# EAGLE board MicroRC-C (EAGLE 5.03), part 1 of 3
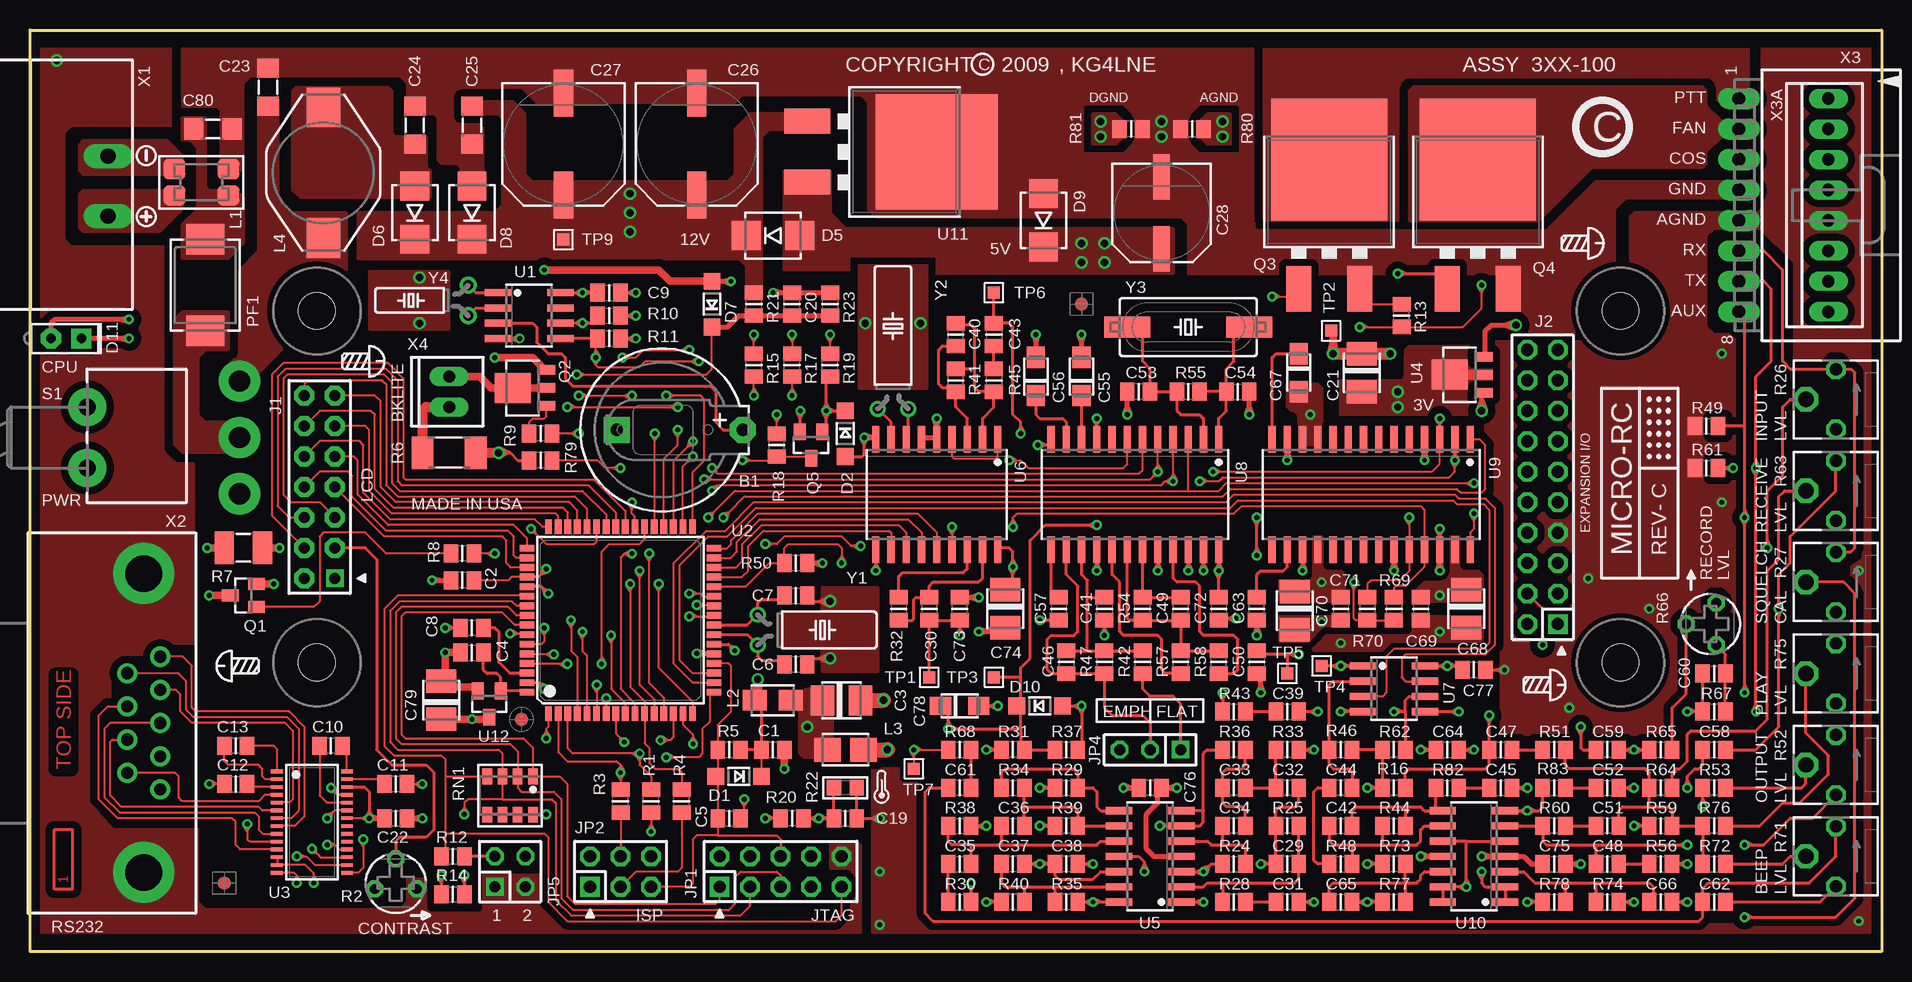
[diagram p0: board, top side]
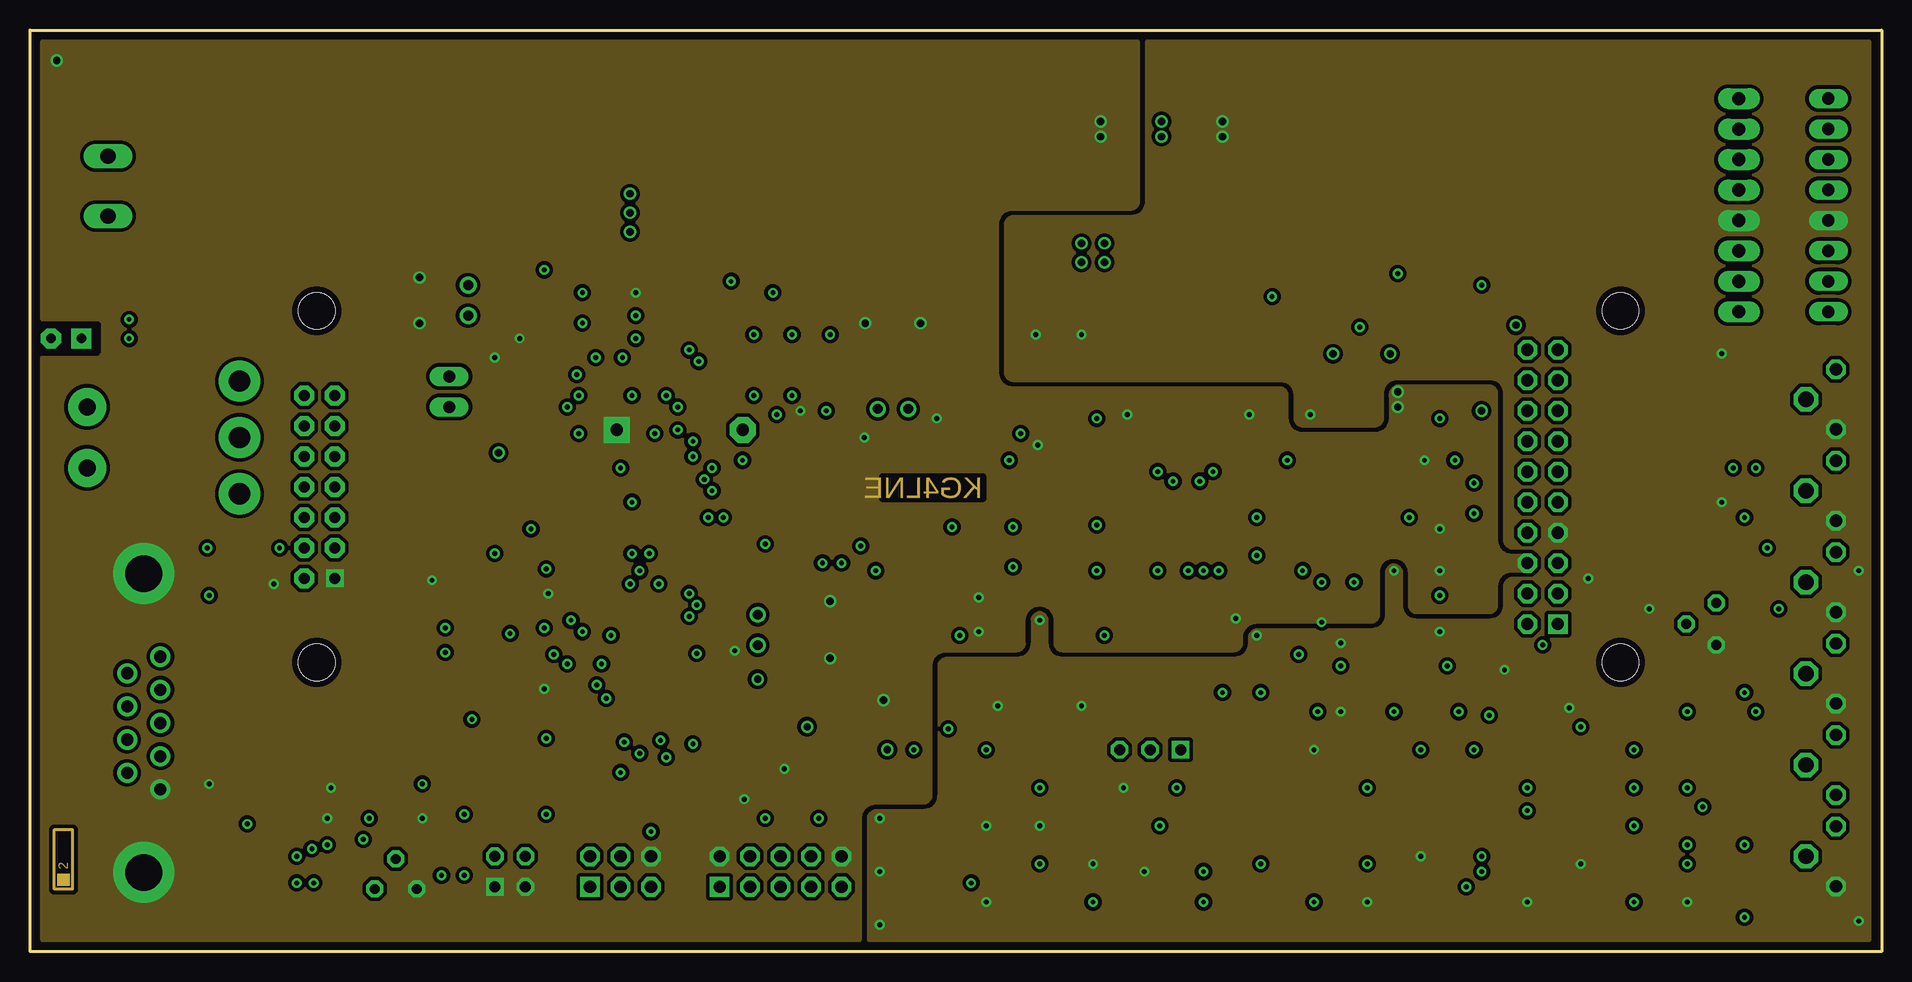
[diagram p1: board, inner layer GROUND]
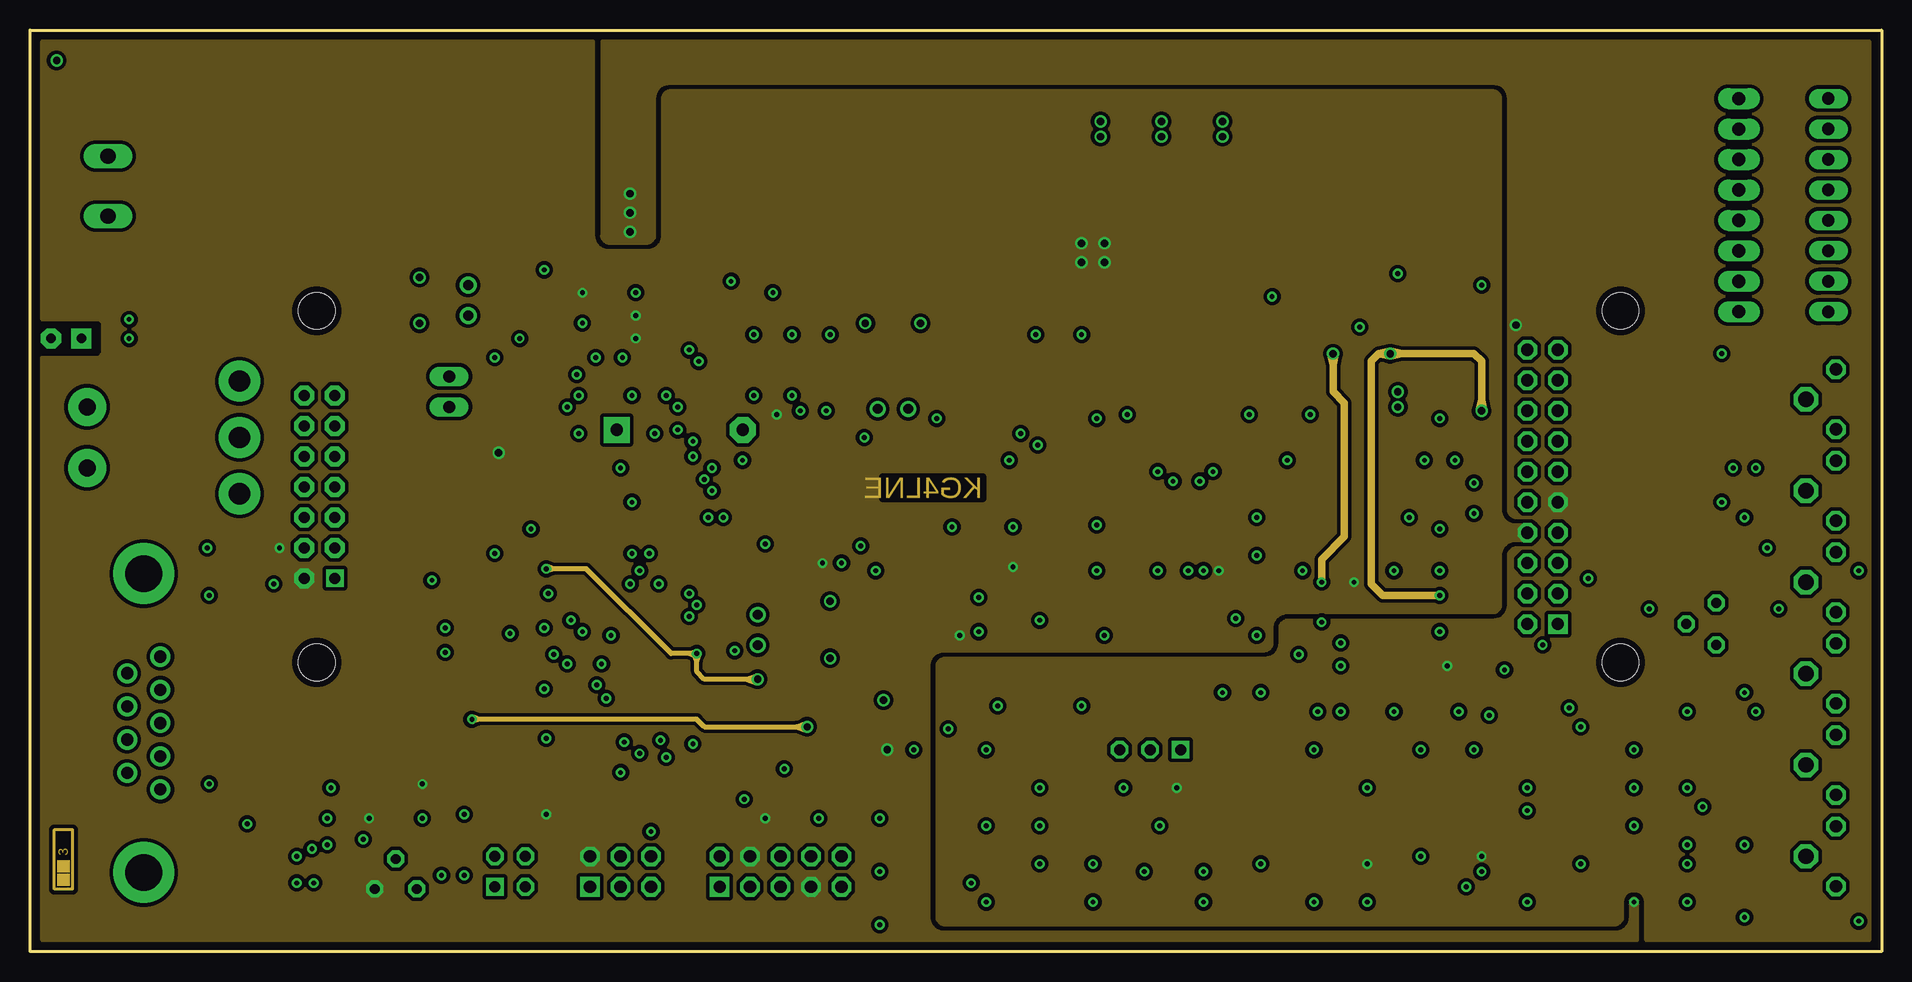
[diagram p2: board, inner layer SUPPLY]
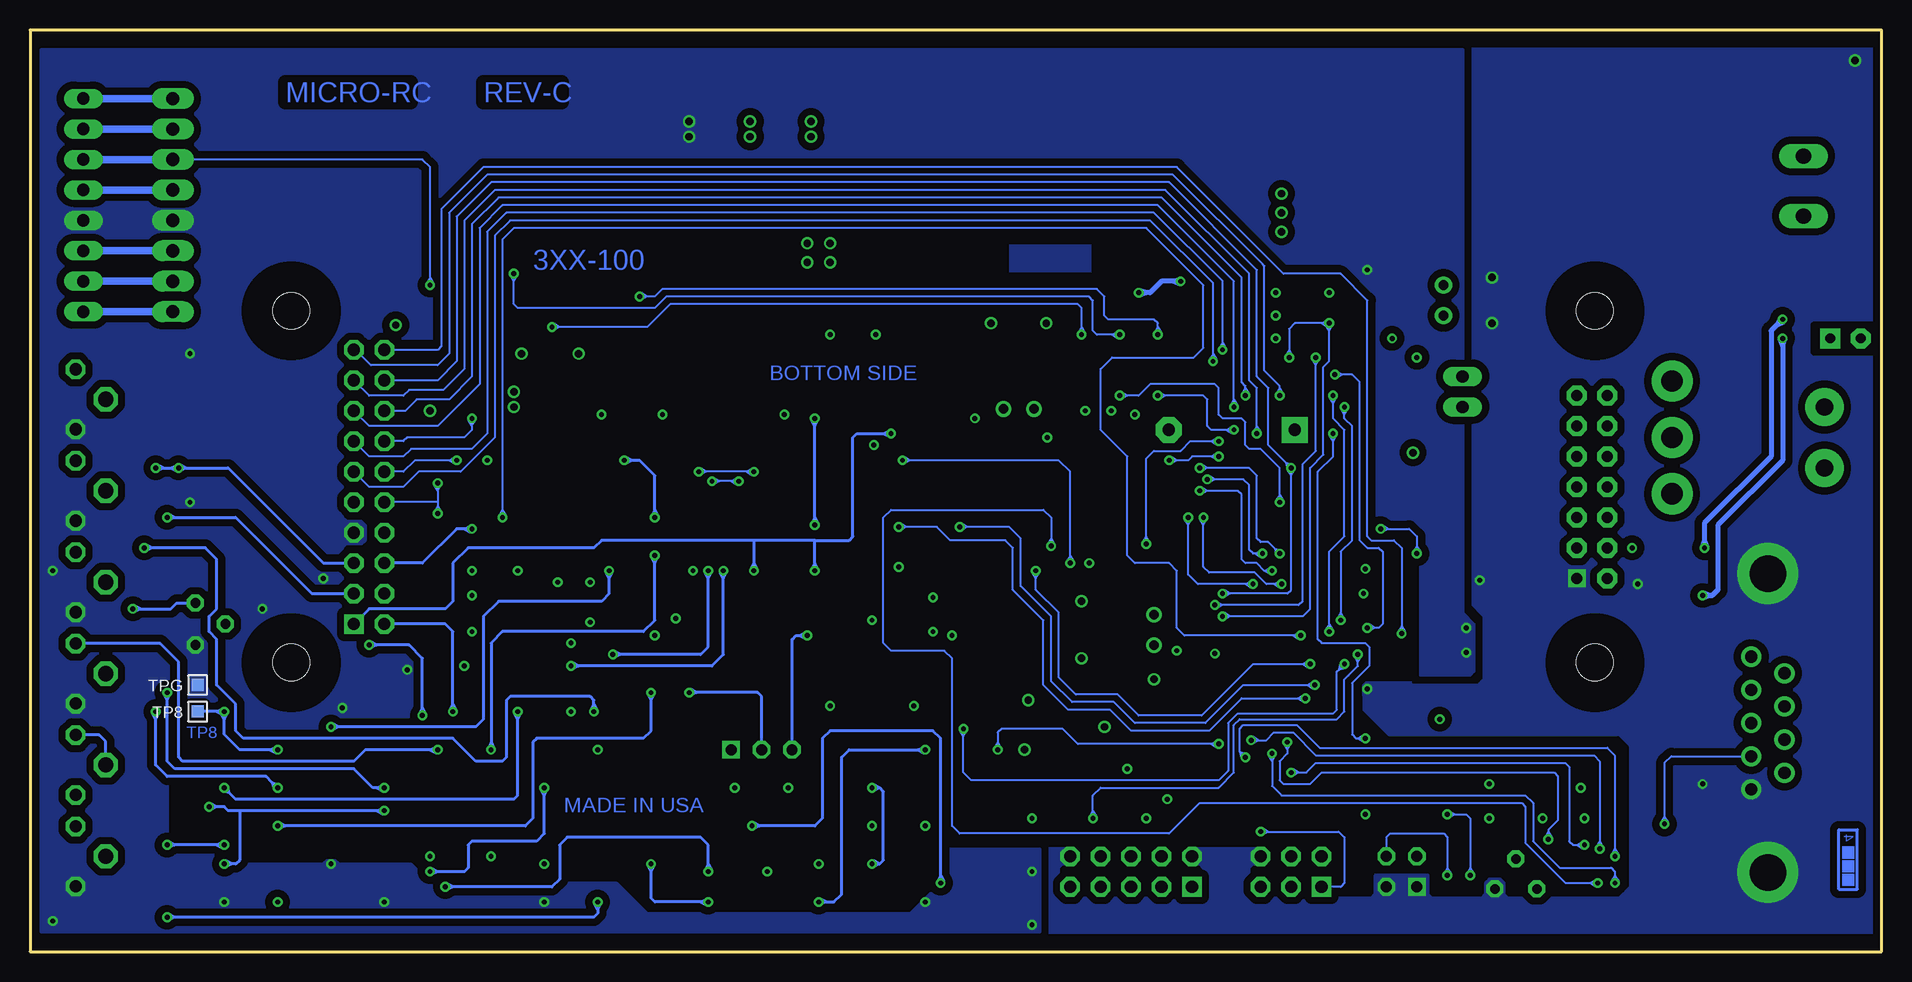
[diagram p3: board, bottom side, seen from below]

Size 154.31 x 76.83 mm. Coordinates in mm from the lower left corner, seen from the top.
Outline: 0,76.83 154.31,76.83 154.31,0 0,0 0,76.83
Copper layers (1*2+3*16): Top 0.035mm / dielectric 0.36mm / GROUND 0.035mm / dielectric 0.71mm / SUPPLY 0.035mm / dielectric 0.36mm / Bottom 0.035mm
Design rules "default *": minimum track width 2mil, minimum drill 16mil, track to track 8mil, track to pad 8mil, pad to pad 8mil, via to via 8mil, smd to smd 8mil, copper to edge 20mil, drill to drill 8mil, minimum pad ring 10mil, minimum via ring 8mil, stop-mask expansion 4mil, vias tented up to drill 32mil, thermal gap 24mil

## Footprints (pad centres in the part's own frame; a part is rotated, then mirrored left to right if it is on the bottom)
BR1225 = drill 1.016 pad 2.159 octagon: + 5.75,0 | drill 1.016 pad 2.159 square: - -4.75,0
C0805 = smd 1.2 x 1.5: 1 -0.953,0; 2 0.953,0
B/3528-21R = smd 1.95 x 2.5: + 1.587,0; - -1.587,0
C1206 = smd 1.6 x 1.8: 1 -1.587,0; 2 1.587,0
PANASONIC_G = smd 3.9 x 1.6: + 4.25,0; - -4.25,0
PANASONIC_E = smd 3.8 x 1.4: + 3,0; - -3,0
A/3216-18R = smd 1.778 x 1.524: + 1.587,0; - -1.587,0
SOD123 = smd 1.4 x 1.4: A 1.905,0; C -1.905,0
SMB = smd 2.4 x 2.4: A 2.223,0; C -2.223,0
LED535 = drill 0.813 pad 1.676 octagon: A -1.27,0 | drill 0.813 pad 1.676 square: K 1.27,0
DMC20261 = drill 0.914 pad 1.422 square: 1 2.54,-7.62 | drill 0.914 pad 1.676 octagon: 2 0,-7.62; 3 2.54,-5.08; 4 0,-5.08; 5 2.54,-2.54; 6 0,-2.54; 7 2.54,0; 8 0,0; 9 2.54,2.54; 10 0,2.54; 11 2.54,5.08; 12 0,5.08; 13 2.54,7.62; 14 0,7.62 | hole 3.048: 1.039,14.683; 1.039,-14.635; 109.674,-14.635; 109.674,14.682
MA10-2 = drill 1.016 square: 1 -11.43,-1.27 | drill 1.016 octagon: 2 -11.43,1.27; 3 -8.89,-1.27; 4 -8.89,1.27; 5 -6.35,-1.27; 6 -6.35,1.27; 7 -3.81,-1.27; 8 -3.81,1.27; 9 -1.27,-1.27; 10 -1.27,1.27; 11 1.27,-1.27; 12 1.27,1.27; 13 3.81,-1.27; 14 3.81,1.27; 15 6.35,-1.27; 16 6.35,1.27; 17 8.89,-1.27; 18 8.89,1.27; 19 11.43,-1.27; 20 11.43,1.27
AVR-JTAG-10 = drill 1.016 square: 1 -5.08,-1.27 | drill 1.016 octagon: 2 -5.08,1.27; 3 -2.54,-1.27; 4 -2.54,1.27; 5 0,-1.27; 6 0,1.27; 7 2.54,-1.27; 8 2.54,1.27; 9 5.08,-1.27; 10 5.08,1.27
AVR-ISP-6 = drill 1.016 square: 1 -2.54,-1.27 | drill 1.016 octagon: 2 -2.54,1.27; 3 0,-1.27; 4 0,1.27; 5 2.54,-1.27; 6 2.54,1.27
JP2 = drill 0.914 square: 1 -2.54,0 | drill 0.914 octagon: 2 0,0; 3 2.54,0
JP2Q = drill 0.914 square: 1 -1.27,-1.27 | drill 0.914 octagon: 2 -1.27,1.27; 3 1.27,-1.27; 4 1.27,1.27
CM1812 = smd 1.841 x 1.689: 1 -2.25,1.1; 2 -2.25,-1.1; 3 2.25,-1.1; 4 2.25,1.1
L1210 = smd 2 x 1.7: 1 -1.5,0; 2 1.5,0
M1331 = smd 2.2 x 2: 1 -1.5,0; 2 1.5,0
PM-13 = smd 3.302 x 2.794: 1 -5.447,0; 2 5.447,0
SMD-7555 = smd 2.54 x 3.175: 1 -3.81,0; 2 3.81,0
SOT23@1 = smd 1 x 1.4: 1 -0.95,-1.1; 2 0.95,-1.1; 3 0,1.1
SOT89 = smd 0.8 x 1.5: 1 -1.5,-1.75; 2 0,-1.75; 3 1.5,-1.75 | smd 2.5 x 3: 4 0,1.05
D2PAK = smd 2.08 x 3.81: 1 -2.54,-8.255; 3 2.54,-8.255 | smd 9.652 x 10.16: 2 0,2.54
R0805 = smd 1.2 x 1.5: 1 -0.953,0; 2 0.953,0
EVM-L4G = drill 0.813 pad 1.422 octagon: 1 -1.75,-0.5; 2 0,2; 3 1.75,-0.5
R2010 = smd 1.8 x 2.7: 1 -2.223,0; 2 2.223,0
R1210 = smd 1.6 x 2.7: 1 -1.587,0; 2 1.587,0
R0805' = smd 1.2 x 1.3: 1 -0.953,0; 2 0.953,0
EVME-SIDE = drill 1.016 octagon: 1 -2.5,0; 3 2.5,0 | drill 1.27 octagon: 2 0,2.5
744-8 = smd 0.8 x 1.3: 1 -1.905,-1.587; 2 -0.635,-1.587; 3 0.635,-1.587; 4 1.905,-1.587; 5 1.905,1.587; 6 0.635,1.587; 7 -0.635,1.587; 8 -1.905,1.587
CK-A = drill 1.778 pad 3.429 round: 1 8.89,-4.699; 2 8.89,0; 3 8.89,4.699 | drill 1.422 pad 3.175 round: B1 -3.81,-2.54; B2 -3.81,2.54
TP10SQ = smd 1 x 1: TP 0,0
SO08 = smd 0.6 x 2.2: 1 -1.905,-2.6; 2 -0.635,-2.6; 3 0.635,-2.6; 4 1.905,-2.6; 5 1.905,2.6; 6 0.635,2.6; 7 -0.635,2.6; 8 -1.905,2.6
TQFP64-AEB = smd 1.194 x 0.559: 1 -7.8,6; 2 -7.8,5.2; 3 -7.8,4.4; 4 -7.8,3.6; 5 -7.8,2.8; 6 -7.8,2; 7 -7.8,1.2; 8 -7.8,0.4; 9 -7.8,-0.4; 10 -7.8,-1.2; 11 -7.8,-2; 12 -7.8,-2.8; 13 -7.8,-3.6; 14 -7.8,-4.4; 15 -7.8,-5.2; 16 -7.8,-6; 33 7.8,-6; 34 7.8,-5.2; 35 7.8,-4.4; 36 7.8,-3.6; 37 7.8,-2.8; 38 7.8,-2; 39 7.8,-1.2; 40 7.8,-0.4; 41 7.8,0.4; 42 7.8,1.2; 43 7.8,2; 44 7.8,2.8; 45 7.8,3.6; 46 7.8,4.4; 47 7.8,5.2; 48 7.8,6 | smd 0.559 x 1.194: 17 -6,-7.8; 18 -5.2,-7.8; 19 -4.4,-7.8; 20 -3.6,-7.8; 21 -2.8,-7.8; 22 -2,-7.8; 23 -1.2,-7.8; 24 -0.4,-7.8; 25 0.4,-7.8; 26 1.2,-7.8; 27 2,-7.8; 28 2.8,-7.8; 29 3.6,-7.8; 30 4.4,-7.8; 31 5.2,-7.8; 32 6,-7.8; 49 6,7.8; 50 5.2,7.8; 51 4.4,7.8; 52 3.6,7.8; 53 2.8,7.8; 54 2,7.8; 55 1.2,7.8; 56 0.4,7.8; 57 -0.4,7.8; 58 -1.2,7.8; 59 -2,7.8; 60 -2.8,7.8; 61 -3.6,7.8; 62 -4.4,7.8; 63 -5.2,7.8; 64 -6,7.8
TSSOP28 = smd 0.305 x 0.991: 1 -4.225,-2.918; 2 -3.575,-2.918; 3 -2.925,-2.918; 4 -2.275,-2.918; 5 -1.625,-2.918; 6 -0.975,-2.918; 7 -0.325,-2.918; 8 0.325,-2.918; 9 0.975,-2.918; 10 1.625,-2.918; 11 2.275,-2.918; 12 2.925,-2.918; 13 3.575,-2.918; 14 4.225,-2.918; 15 4.225,2.918; 16 3.575,2.918; 17 2.925,2.918; 18 2.275,2.918; 19 1.625,2.918; 20 0.975,2.918; 21 0.325,2.918; 22 -0.325,2.918; 23 -0.975,2.918; 24 -1.625,2.918; 25 -2.275,2.918; 26 -2.925,2.918; 27 -3.575,2.918; 28 -4.225,2.918
SO14 = smd 0.6 x 2.2: 1 -3.81,-2.6; 2 -2.54,-2.6; 3 -1.27,-2.6; 4 0,-2.6; 5 1.27,-2.6; 6 2.54,-2.6; 7 3.81,-2.6; 8 3.81,2.6; 9 2.54,2.6; 10 1.27,2.6; 11 0,2.6; 12 -1.27,2.6; 13 -2.54,2.6; 14 -3.81,2.6
SO18W = smd 0.6 x 2.2: 1 -5.08,-4.6; 2 -3.81,-4.6; 3 -2.54,-4.6; 4 -1.27,-4.6; 5 0,-4.6; 6 1.27,-4.6; 7 2.54,-4.6; 8 3.81,-4.6; 9 5.08,-4.6; 10 5.08,4.6; 11 3.81,4.6; 12 2.54,4.6; 13 1.27,4.6; 14 0,4.6; 15 -1.27,4.6; 16 -2.54,4.6; 17 -3.81,4.6; 18 -5.08,4.6
SO24W = smd 0.6 x 2.2: 1 -6.985,-4.6; 2 -5.715,-4.6; 3 -4.445,-4.6; 4 -3.175,-4.6; 5 -1.905,-4.6; 6 -0.635,-4.6; 7 0.635,-4.6; 8 1.905,-4.6; 9 3.175,-4.6; 10 4.445,-4.6; 11 5.715,-4.6; 12 6.985,-4.6; 13 6.985,4.6; 14 5.715,4.6; 15 4.445,4.6; 16 3.175,4.6; 17 1.905,4.6; 18 0.635,4.6; 19 -0.635,4.6; 20 -1.905,4.6; 21 -3.175,4.6; 22 -4.445,4.6; 23 -5.715,4.6; 24 -6.985,4.6
SO28W = smd 0.6 x 2.2: 1 -8.255,-4.6; 2 -6.985,-4.6; 3 -5.715,-4.6; 4 -4.445,-4.6; 5 -3.175,-4.6; 6 -1.905,-4.6; 7 -0.635,-4.6; 8 0.635,-4.6; 9 1.905,-4.6; 10 3.175,-4.6; 11 4.445,-4.6; 12 5.715,-4.6; 13 6.985,-4.6; 14 8.255,-4.6; 15 8.255,4.6; 16 6.985,4.6; 17 5.715,4.6; 18 4.445,4.6; 19 3.175,4.6; 20 1.905,4.6; 21 0.635,4.6; 22 -0.635,4.6; 23 -1.905,4.6; 24 -3.175,4.6; 25 -4.445,4.6; 26 -5.715,4.6; 27 -6.985,4.6; 28 -8.255,4.6
SOT23 = smd 1 x 1.4: 1 -0.95,-1.1; 2 0.95,-1.1; 3 0,1.1
951-2 = drill 1.27 pad 1.93 long: 1 -2.5,0; 2 2.5,0
NC182M9 = drill 1.016 pad 1.676 round: 1 -5.537,2.769; 2 -2.769,2.769; 3 0,2.769; 4 2.769,2.769; 5 5.537,2.769; 6 -4.153,0; 7 -1.384,0; 8 1.384,0; 9 4.153,0 | drill 3.048 pad 5.08 round: G1 12.459,1.384; G2 -12.459,1.384
70553-08 = drill 1.092 long: 1 -8.89,-7.62; 2 -6.35,-7.62; 3 -3.81,-7.62; 4 -1.27,-7.62; 5 1.27,-7.62; 6 3.81,-7.62; 7 6.35,-7.62; 8 8.89,-7.62
MTA08-100 = drill 1.016 long: 1 8.89,0; 2 6.35,0; 3 3.81,0; 4 1.27,0; 5 -1.27,0; 6 -3.81,0; 7 -6.35,0; 8 -8.89,0
MTA-100-2V = drill 1.016 long: 1 -1.27,0; 2 1.27,0
TC38H = drill 0.813 round: 1 -1.27,0; 2 1.27,0
TC310H = drill 0.813 round: 1 -1.27,0; 2 1.27,0
SM49 = smd 3.81 x 1.778: 1 -5.08,0; 2 5.08,0
TC26H = drill 0.813 pad 1.422 round: 1 -1.27,0; 2 1.27,0

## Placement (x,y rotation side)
ASSY1  3XX-100  [FIELD_ASSY_NUM]  119.38,73.34 0 top
B1  BR1225A/HB  [BR1225]  53.66,43.5 0 top
C1  1uf  [C0805]  61.91,16.83 0 top
C2  0.1uf  [C0805]  36.04,30.96 180 top
C3  10uf/16V  [B/3528-21R]  67.63,20.95 180 top
C4  10uf  [C0805]  36.83,24.92 0 top
C5  .01uf  [C0805]  58.26,11.11 0 top
C6  22pf  [C0805]  63.82,23.95 0 top
C7  22pf  [C0805]  63.82,29.67 0 top
C8  0.1uf  [C0805]  36.83,26.99 180 top
C9  0.1uf  [C0805]  48.26,54.93 0 top
C10  1uf  [C0805]  25.08,17.14 180 top
C11  1uf  [C0805]  30.48,13.97 180 top
C12  1uf  [C0805]  17.14,13.97 0 top
C13  1uf  [C0805]  17.14,17.14 180 top
C19  0.1uf  [C0805]  67.94,11.11 0 top
C20  0.1uf  [C0805]  63.5,53.97 90 top
C21  10uf/16V  [B/3528-21R]  110.97,48.26 90 top
C22  1uf  [C0805]  30.48,11.11 0 top
C23  0.1uf  [C1206]  19.84,72.07 90 top
C24  0.1uf  [C1206]  32.07,68.9 90 top
C25  0.1uf  [C1206]  36.83,68.9 270 top
C26  470uf/25V  [PANASONIC_G]  55.56,67.31 270 top
C27  470uf/25V  [PANASONIC_G]  44.45,67.31 270 top
C28  100uf/16V  [PANASONIC_E]  94.3,61.59 270 top
C29  100pf  [C0805]  104.78,7.3 180 top
C30  0.1uf  [C0805]  74.93,28.57 270 top
C31  0.1uf  [C0805]  104.78,4.13 180 top
C32  1500pf  [C0805]  104.78,13.65 180 top
C33  1500pf  [C0805]  100.33,13.65 180 top
C34  1500pf  [C0805]  100.33,10.48 180 top
C35  0.047uf  [C0805]  77.47,7.3 0 top
C36  470pf  [C0805]  81.92,10.48 0 top
C37  470pf  [C0805]  81.92,7.3 180 top
C38  0.047uf  [C0805]  86.36,7.3 180 top
C39  1uf  [C0805]  104.78,20 0 top
C40  1000pf  [C0805]  77.15,51.43 90 top
C41  .0068uf  [C0805]  89.53,28.57 270 top
C42  1500pf  [C0805]  109.22,10.48 0 top
C43  0.1uf  [C0805]  80.33,51.43 270 top
C44  1uf  [C0805]  109.22,13.65 180 top
C45  1uf  [C0805]  122.56,13.65 0 top
C46  100pf  [C0805]  86.36,24.13 270 top
C47  1uf  [C0805]  122.56,16.83 0 top
C48  560pf  [C0805]  131.44,7.3 0 top
C49  100pf  [C0805]  95.89,28.57 90 top
C50  1uf  [C0805]  102.23,24.13 270 top
C51  10uf  [C0805]  131.44,10.48 180 top
C52  1uf  [C0805]  131.44,13.65 0 top
C53  33pf  [C0805]  92.39,46.67 180 top
C54  33pf  [C0805]  100.65,46.67 0 top
C55  0.1uf/35V  [A/3216-18R]  87.63,47.94 270 top
C56  2.2uf/10V  [A/3216-18R]  83.82,47.94 270 top
C57  0.1uf  [C0805]  85.72,28.57 270 top
C58  1uf  [C0805]  140.34,16.83 0 top
C59  1uf  [C0805]  131.44,16.83 180 top
C60  4700pf  [C0805]  140.34,23.18 0 top
C61  1uf  [C0805]  77.47,13.65 180 top
C62  0.001uf  [C0805]  140.34,4.13 0 top
C63  0.1uf  [C0805]  102.23,28.57 90 top
C64  1uf  [C0805]  118.11,16.83 0 top
C65  2.2uf  [C0805]  109.22,4.13 0 top
C66  2.2uf  [C0805]  135.89,4.13 0 top
C67  1uf/16V  [A/3216-18R]  105.73,48.26 90 top
C68  22uf/16V  [B/3528-21R]  119.7,28.57 90 top
C69  0.1uf  [C0805]  115.89,28.57 270 top
C70  22uf/16V  [B/3528-21R]  105.41,28.42 90 top
C71  0.1uf  [C0805]  109.22,28.57 270 top
C72  0.1uf  [C0805]  99.06,28.57 270 top
C73  0.1uf  [C0805]  77.47,28.57 90 top
C74  22uf/16V  [B/3528-21R]  81.28,28.57 90 top
C75  0.1uf  [C0805]  127,7.3 0 top
C76  0.1uf  [C0805]  93.34,13.65 180 top
C77  0.1uf  [C0805]  120.33,23.49 0 top
C78  0.1uf/35V (DNP)  [A/3216-18R]  77.47,20.48 180 top
C79  10uf/16V  [B/3528-21R]  34.29,20.96 270 top
C80  0.01uf  [C1206]  15.24,68.58 0 top
D1  BAV16W-7-F  [SOD123]  59.05,14.6 180 top
D2  BZT52C5V1-7-F  [SOD123]  67.94,43.18 270 top
D5  S1GB-13  [SMB]  61.91,59.69 0 top
D6  S1GB-13  [SMB]  32.07,61.59 90 top
D7  BZT52C5V6-7-F  [SOD123]  56.83,53.97 90 top
D8  1SMB5931BT3G  [SMB]  36.83,61.59 90 top
D9  S1GB-13  [SMB]  84.45,60.96 90 top
D10  BZT52C5V1-7-F  [SOD123]  84.14,20.48 0 top
D11  RED  [LED535]  3.02,51.12 0 top
DATECODE1  A0709  [FIELD_DATECODE5_RESTRICT]  72.07,57.15 0 bottom
FIDUCIAL1  FIDUCIAL-G10S  [G10S]  16.19,5.71 0 top
FIDUCIAL2  FIDUCIAL-G10S  [G10S]  87.63,53.97 0 top
FIDUCIAL3  FIDUCIAL-G10  [G10]  40.96,19.37 0 top
J1  DMC20261  [DMC20261]  22.86,38.73 0 top
J2  [MA10-2]  126.05,38.73 90 top
JP1  AVR-JTAG-10  [AVR-JTAG-10]  62.55,6.67 0 top
JP2  AVR-ISP-6  [AVR-ISP-6]  49.21,6.67 0 top
JP4  [JP2]  93.34,16.83 180 top
JP5  [JP2Q]  40.01,6.67 0 top
L1  CM1812  [CM1812]  14.29,64.13 0 top
L2  0.1uH  [L1210]  61.91,20.95 180 top
L3  FB-M1331  [M1331]  67.94,16.83 0 top
L4  10uH  [PM-13]  24.45,64.93 90 top
PF1  MF-SM030-2  [SMD-7555]  14.61,55.56 270 top
Q1  MMBTA05LT1G  [SOT23@1]  17.78,29.69 90 top
Q2  ZXMN6A07Z  [SOT89]  41.27,46.99 90 top
Q3  IRF614SPBF  [D2PAK]  108.27,63.5 0 top
Q4  IRF614SPBF  [D2PAK]  120.65,63.5 0 top
Q5  MMBTA05LT1G  [SOT23@1]  65.09,42.23 180 top
R1  47.5  [R0805]  51.75,12.54 90 top
R2  10K  [EVM-L4G]  30.48,5.71 0 top
R3  47.5  [R0805]  49.21,12.54 90 top
R4  47.5  [R0805]  54.29,12.54 90 top
R5  10K  [R0805]  58.26,16.83 0 top
R6  48.7/0.5W  [R2010]  34.92,41.59 180 top
R7  464/0.25W  [R1210]  17.78,33.65 180 top
R8  4.75K  [R0805]  36.04,33.18 180 top
R9  4.75K  [R0805]  42.55,43.18 180 top
R10  10K  [R0805]  48.26,53.02 0 top
R11  10K  [R0805]  48.26,51.12 0 top
R12  47.5  [R0805]  35.24,7.94 0 top
R13  100K  [R0805]  114.3,53.02 90 top
R14  47.5  [R0805]  35.24,4.76 0 top
R15  4.75K  [R0805]  60.33,48.89 90 top
R16  1M  [R0805]  113.67,13.65 180 top
R17  4.75K  [R0805]  63.5,48.89 90 top
R18  10K  [R0805]  62.23,42.23 90 top
R19  4.75K  [R0805]  66.67,48.89 90 top
R20  100K  [R0805]  63.5,11.11 180 top
R21  62K  [R0805]  60.33,53.97 90 top
R22  NCP21WF104J03RA  [R0805']  67.94,13.65 180 top
R23  22K  [R0805]  66.67,53.97 270 top
R24  91.0K  [R0805]  100.33,7.3 0 top
R25  10K  [R0805]  104.78,10.48 180 top
R26  10K  [EVME-SIDE]  150.5,46.04 90 top
R27  10K  [EVME-SIDE]  150.5,30.8 90 top
R28  10K  [R0805]  100.33,4.13 180 top
R29  332K  [R0805]  86.36,13.65 0 top
R30  4.75K  [R0805]  77.47,4.13 0 top
R31  22K  [R0805]  81.92,16.83 180 top
R32  301K  [R0805]  72.39,28.57 270 top
R33  4.75K  [R0805]  104.78,16.83 180 top
R34  100K  [R0805]  81.92,13.65 0 top
R35  150K  [R0805]  86.36,4.13 180 top
R36  5.62K  [R0805]  100.33,16.83 180 top
R37  100K  [R0805]  86.36,16.83 0 top
R38  8.25K  [R0805]  77.47,10.48 0 top
R39  10K  [R0805]  86.36,10.48 180 top
R40  10K  [R0805]  81.92,4.13 180 top
R41  100K  [R0805]  77.15,47.62 90 top
R42  11.3K  [R0805]  92.71,24.13 270 top
R43  10K  [R0805]  100.33,20 0 top
R44  22K  [R0805]  113.67,10.48 0 top
R45  100K  [R0805]  80.33,47.62 270 top
R46  1M  [R0805]  109.22,16.83 0 top
R47  93.1K  [R0805]  89.53,24.13 270 top
R48  22K  [R0805]  109.22,7.3 0 top
R49  100K  [R0805]  139.7,43.81 0 top
R50  10K  [R0805]  63.82,32.38 180 top
R51  22K  [R0805]  127,16.83 0 top
R52  200K  [EVME-SIDE]  150.5,15.56 90 top
R53  33.2K  [R0805]  140.34,13.65 180 top
R54  10K  [R0805]  92.71,28.57 90 top
R55  1M  [R0805]  96.52,46.67 180 top
R56  10K  [R0805]  135.89,7.3 0 top
R57  10K  [R0805]  95.89,24.13 90 top
R58  10K  [R0805]  99.06,24.13 90 top
R59  22K  [R0805]  135.89,10.48 0 top
R60  33.2K  [R0805]  127,10.48 180 top
R61  100K  [R0805]  139.7,40.32 0 top
R62  1M  [R0805]  113.67,16.83 180 top
R63  10K  [EVME-SIDE]  150.5,38.42 90 top
R64  22K  [R0805]  135.89,13.65 180 top
R65  10K  [R0805]  135.89,16.83 0 top
R66  10K  [EVM-L4G]  140.02,27.3 90 top
R67  10K  [R0805]  140.34,20 0 top
R68  100K  [R0805]  77.47,16.83 0 top
R69  10K  [R0805]  113.67,28.57 270 top
R70  10K  [R0805]  111.44,28.57 270 top
R71  10K  [EVME-SIDE]  150.5,7.94 90 top
R72  22K  [R0805]  140.34,7.3 0 top
R73  100K  [R0805]  113.67,7.3 180 top
R74  100K  [R0805]  131.44,4.13 0 top
R75  10K  [EVME-SIDE]  150.5,23.18 90 top
R76  22K  [R0805]  140.34,10.48 180 top
R77  100K  [R0805]  113.67,4.13 0 top
R78  100K  [R0805]  127,4.13 0 top
R79  10K  [R0805]  42.55,40.96 180 top
R80  0R  [R0805]  96.84,68.58 0 top
R81  0R  [R0805]  91.76,68.58 180 top
R82  1.00K  [R0805]  118.11,13.65 0 top
R83  1.00K  [R0805]  127,13.65 0 top
REV1  C  [FIELD_REV-M]  131.13,68.76 0 top
RN1  10K  [744-8]  40.01,13.02 180 top
S1  CK-A  [CK-A]  8.57,42.86 0 top
TP1  TPTP10SQ  [TP10SQ]  74.93,22.86 270 top
TP2  TPTP10SQ  [TP10SQ]  108.43,51.75 180 top
TP3  TPTP10SQ  [TP10SQ]  80.33,22.86 270 top
TP4  TPTP10SQ  [TP10SQ]  107.63,23.81 90 top
TP5  TPTP10SQ  [TP10SQ]  104.78,23.18 90 top
TP6  TPTP10SQ  [TP10SQ]  80.33,54.93 90 top
TP7  TPTP10SQ  [TP10SQ]  73.66,15.24 270 top
TP8  TPTP10SQ  [TP10SQ]  140.34,20 180 bottom
TP9  TPTP10SQ  [TP10SQ]  44.45,59.37 0 top
TPG  TPTP10SQ  [TP10SQ]  140.34,22.22 180 bottom
U1  DS1307Z  [SO08]  41.59,53.02 270 top
U2  MEGA1281/2561  [TQFP64-AEB]  49.21,27.62 90 top
U3  MAX3243PW  [TSSOP28]  23.5,10.79 270 top
U4  L78LXXCU/BU  [SOT89]  119.38,48.1 90 top
U5  LM324D  [SO14]  93.34,7.94 90 top
U6  CM8870CS  [SO18W]  75.56,38.1 180 top
U7  MAX323CSA  [SO08]  113.67,21.91 270 top
U8  MX828DW  [SO24W]  92.08,38.1 180 top
U9  ISD4002S  [SO28W]  111.76,38.1 180 top
U10  TL084D  [SO14]  120.33,7.94 90 top
U11  L78XXD2T  [D2PAK]  73.03,66.67 270 top
U12  AD158X  [SOT23]  38.26,20.64 180 top
U$6  , KG4LNE  [FIELD_COPYRIGHT]  67.94,73.34 0 top
U$7  LAYER-CHECK-4  [LAYER_CHECK-4]  3.17,5.71 90 top
U$74  [ICON_SIDE_BOTTOM]  92.71,47.62 0 top
U$75  [ICON_SIDE_TOP]  3.43,15.18 90 top
U$96  C  [FIELD_VERSION]  136.37,33.02 90 top
U$112  [ICON_TEMP]  70.96,13.02 0 top
U$123  [ICON_MINUS]  9.68,66.36 90 top
U$125  [ICON_PLUS]  9.68,61.28 0 top
U$133  [ICON_MSCREW-S]  129.86,59.05 270 top
U$230  [ICON_PIN1_B]  127.64,25.4 270 top
U$235  [ICON_PIN1_B]  27.3,31.11 0 top
U$239  [ICON_MSCREW-S]  126.68,22.22 270 top
U$240  [ICON_ARROW-T]  33.34,3.02 270 top
U$241  [ICON_ARROW-T]  138.43,31.75 0 top
U$280  [ICON_PIN1_B]  46.67,3.49 270 top
U$281  [ICON_PIN1_B]  57.47,3.49 270 top
U$282  [ICON_MSCREW-S]  16.83,23.81 90 top
U$283  [ICON_MSCREW-S]  28.26,49.21 270 top
X1  EDSTLZ951/2  [951-2]  6.51,63.82 270 top
X2  182-009-112-531  [NC182M9]  8.1,19.05 270 top
X3  70553-0007  [70553-08]  150.02,62.23 270 top
X3A  [MTA08-100]  149.86,62.23 90 top
X4  [MTA-100-2V]  34.92,46.67 90 top
Y1  16.000 MHz  [TC38H]  60.64,26.81 270 top
Y2  3.579 MHZ  [TC310H]  71.91,45.24 0 top
Y3  4.032MHZ  [SM49]  96.52,52.07 0 top
Y4  32.678 kHz  [TC26H]  36.51,54.29 90 top

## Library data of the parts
ASSY1 DATECODE1 REV1 U$6 U$74 U$75 U$96 U$112 U$123 U$125 U$133 U$230 U$235 U$239-U$241 U$280-U$283 = dicons
B1 = battery
C1-C13 C19-C80 L2 L3 R1 R3-R21 R23-R25 R28-R51 R53-R62 R64 R65 R67-R70 R72-R74 R76-R83 = rcl
D1 D2 D5-D10 = diode
D11 = led; PARTNUM: 5350T5
FIDUCIAL1-FIDUCIAL3 U$7 = dfiducial
J1 = display-lcd
J2 = con-lstb
JP1 JP2 U2 = atmel
JP4 JP5 = jumper
L1 = inductor-steward
L4 = inductors-jwmiller
PF1 = fuse
Q1 Q5 = transistor-npn
Q2 = zetex
Q3 Q4 = transistor-fet
R2 R26 R27 R52 R63 R66 R71 R75 = pot
R22 = ptc-ntc
RN1 = resistor-array
S1 = switch
TP1-TP9 TPG = testpad
U1 U3 U7 = maxim
U4 U11 U12 = v-reg
U5 U6 U10 = linear
U8 = cml-micro
U9 = isd
X1 = con-ost
X2 = con-subd
X3 X4 = con-hdrs40
X3A = con-amp
Y1-Y4 = crystal

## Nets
+2V5: R16.2 R46.2 R62.2 U10.1 U10.2
+3V3: C21.+ C68.+ C69.1 C70.+ C71.1 TP2.TP U4.1 U9.18 U9.27
+5V: C9.1 C11.1 C22.1 C28.+ C30.2 C72.1 C73.1 C74.+ D5.A D9.C J1.2 J2.8 JP1.4 JP1.7 JP2.2 L3.2 R2.1 R6.1 R7.1 R10.2 R11.2 R18.2 R20.2 R50.1 R69.2 R70.2 R74.2 R79.2 RN1.5 RN1.6 RN1.7 RN1.8 TP1.TP U1.8 U3.22 U3.26 U6.18 U8.24 U11.3
+12V: C25.1 C26.+ C27.+ C75.1 C76.1 C77.1 D5.C D6.C D8.C J2.9 R21.2 R73.2 TP9.TP U4.3 U5.4 U7.8 U10.4 U11.1
AGND: C4.1 C8.2 C19.2 C20.2 C38.1 C55.- C56.- C57.2 C60.2 C62.2 C63.1 C65.2 C66.2 C67.- C68.- C69.2 C75.2 C76.2 C77.2 C78.- C79.- D7.A D10.A J2.7 R22.1 R23.1 R26.1 R27.1 R33.1 R37.2 R38.2 R39.2 R40.2 R49.1 R61.1 R63.1 R66.1 R67.2 R71.1 R75.1 R77.1 R78.1 R80.2 TPG.TP U5.11 U7.4 U9.11 U9.12 U9.23 U10.11 U12.2 X3.5 X3A.5
AUX_AUDIO: C45.2 J2.3 R49.2 X3.8 X3A.8
AUX_AUDIO_OUT: TP4.TP U7.1 U8.22
AVR_5V: C1.1 C2.1 D1.C L2.2 R5.2 U2.21 U2.52
AVR_REF: C4.2 U2.64 U12.1
B_CTS: U3.6 X2.8
B_DCD: U3.8 X2.1
B_DSR: U3.7 X2.6
B_DTR: U3.10 X2.4
B_RI: U3.4 X2.9
B_RTS: U3.11 X2.7
B_RXD: U3.5 X2.2
B_TXD: U3.9 X2.3
BEEP_PWM: R68.1 TP7.TP U2.15
CGND: C23.2 C24.2 C25.2 C26.- C27.- C28.- C80.2 D8.A D9.A L1.4 Q3.3 Q4.3 R13.2 R80.1 R81.1 U11.2 X3.4 X3A.4
COM_CTS: U2.14 U3.17
COM_DCD: U2.8 U3.15
COM_DSR: U2.17 U3.16
COM_DTR: U2.35 U3.12 U3.13
COM_RXD: R3.2 U2.2 U3.18
COM_TXD: R1.2 U2.3 U3.14
COS: R13.1 R19.2 X3.3 X3A.3
CS_DTMF: U2.38 U6.10
DISC_AUDIO: R26.3 R27.3 X3.6 X3A.6
DTMF_Q1: U2.29 U6.11
DTMF_Q2: U2.30 U6.12
DTMF_Q3: U2.31 U6.13
DTMF_Q4: U2.32 U6.14
EXP_IO0: J2.15 U2.4
EXP_IO1: J2.19 U2.5
EXP_IO2: J2.17 U2.37
EXT_COS: Q5.3 R18.1 U2.34
FAN: Q4.2 X3.2 X3A.2
FAN_DRIVE: R17.1 U2.39
GND: B1.- C1.2 C2.2 C3.- C5.2 C6.2 C7.2 C9.2 C12.1 C21.- C22.2 C53.2 C54.2 C70.- C71.2 C72.2 C73.2 C74.- D2.A J1.1 J2.6 JP1.2 JP1.10 JP2.6 JP5.1 JP5.3 Q1.2 Q2.3 Q5.2 R2.3 R81.2 U1.4 U2.22 U2.53 U2.63 U3.23 U3.25 U4.2 U4.4 U6.5 U6.6 U6.9 U8.12 U9.4 U9.26 X2.5 X2.G1 X2.G2
I2C_SCL: J2.13 R10.1 U1.6 U2.25
I2C_SDA: J2.11 R11.1 U1.5 U2.26
INT_DTMF: U2.6 U6.15
INT_EXP: J2.18 R79.1 U2.27
INT_ISD: R69.1 U2.7 U9.25
INT_MX828: R50.2 U2.28 U8.7
ISD_RAC: R70.1 U2.9 U9.24
LCD_BKLITE: R9.1 U2.1
LCD_E: J1.6 U2.41
LCD_RS: J1.4 U2.40
LCD_RW: J1.5 U2.42
LED_PWR: R8.1 U2.43
MIX_BUSS: C51.1 R51.2 R59.2 R64.2 R72.1 R76.2
MIX_INSERT: C47.1 J2.4 R16.1
MUTE_AUX: U2.18 U7.7
MUTE_RX: U2.19 U7.3
N$1: L1.1 X1.1
N$2: C8.1 U2.62
N$3: C45.1 R82.2
N$4: C39.2 R26.2
N$5: C58.1 R62.1 U7.6
N$6: R63.2 R64.1
N$7: R65.2 R66.2
N$8: C63.2 U9.16
N$9: JP5.2 R12.2
N$10: C56.+ U8.11
N$11: C52.1 R83.2
N$12: JP4.1 R42.2
N$13: C23.1 L4.1 S1.3
N$14: L1.2 X1.2
N$15: C59.1 C60.1 R65.1 R67.1 TP8.TP
N$16: U6.7 Y2.2
N$17: U6.8 Y2.1
N$18: U6.1 U6.4
N$19: C24.1 D6.A L4.2
N$20: U1.1 Y4.2
N$21: U1.2 Y4.1
N$22: C61.1 R68.2
N$23: R75.2 R76.1
N$24: C65.1 R73.1 R77.2 U10.12
N$25: C64.2 R75.3
N$26: C40.2 R41.2 R45.2 U6.2
N$27: C41.2 JP4.3
N$28: C40.1 R41.1 U6.3
N$29: C30.1 R32.2 U6.17
N$30: C7.1 U2.24 Y1.1
N$31: JP5.4 R14.2
N$32: R32.1 U6.16
N$33: C59.2 U9.17
N$34: C12.2 U3.3
N$35: C44.2 R48.1
N$36: C11.2 U3.27
N$37: C64.1 U9.13
N$38: C6.1 U2.23 Y1.2
N$39: C13.1 U3.1
N$40: C43.2 R45.1
N$41: C55.+ U8.10
N$42: C48.2 R56.1
N$43: R30.2 R36.2 U5.6 U5.7
N$44: C10.1 U3.28
N$45: C13.2 U3.2
N$46: C10.2 U3.24
N$47: C31.1 R27.2
N$48: C44.1 R46.1 U7.2
N$49: C61.2 C62.1 R71.3
N$50: R71.2 R72.2
N$52: C53.1 R55.2 U8.2 Y3.1
N$53: C54.1 R55.1 U8.1 Y3.2
N$54: C49.2 R54.2 U8.19
N$55: R53.2 R56.2 R83.1 U10.7
N$56: C39.1 R43.2
N$57: C46.2 JP4.2 R43.1 R47.2 U8.14
N$58: C57.1 U8.13
N$59: C41.1 C46.1 R42.1 R47.1 U8.15
N$60: C48.1 R52.1 R60.2 U10.6
N$61: C58.2 R63.3 R66.3
N$62: C50.2 R59.1
N$63: B1.+ U1.3
N$64: C32.2 C33.1 R33.2
N$66: Q3.1 R15.2
N$67: Q2.1 R9.2
N$68: Q2.2 Q2.4 X4.2
N$69: R6.2 X4.1
N$70: R29.2 R34.1 U5.8
N$72: C36.2 R34.2 R39.1 U5.9
N$73: R57.1 U8.17
N$76: D2.C Q5.1 R19.1
N$77: C35.1 R30.1
N$78: PF1.2 S1.2
N$79: Q4.1 R17.2
N$80: R58.1 U8.21
N$81: C80.1 L1.3 PF1.1
N$82: C34.2 R24.2 U5.5
N$83: R52.2 R52.3 R53.1
N$84: C67.+ U9.14
N$85: C42.1 R44.1 R48.2 U10.9
N$86: C3.+ C79.+ L2.1 L3.1 U12.3
N$87: C42.2 R44.2 R82.1 U10.8
N$88: C33.2 C34.1 R36.1
N$89: C49.1 R54.1 R57.2 R58.2 U8.18
N$90: D11.K Q1.3
N$91: D11.A R7.2
N$92: Q1.1 R8.2
N$93: C47.2 R51.1
N$94: C29.2 C32.1 R25.2 U5.1
N$95: C35.2 C36.1 R38.1 U5.10
N$96: C37.1 C38.2 R29.1 U5.12
N$98: C29.1 R25.1 R28.2 U5.2
N$99: C31.2 R28.1
N$102: C37.2 R35.2 R40.1 U5.13
N$105: JP2.1 R1.1
N$106: C51.2 R60.1
N$107: JP2.3 R4.1
N$108: JP2.4 R3.1
N$109: C66.1 R74.1 R78.2 U10.3
N$111: R31.2 R35.1 U5.14
PA0: J1.7 U2.51
PA1: J1.8 U2.50
PA2: J1.9 U2.49
PA3: J1.10 U2.48
PA4: J1.11 U2.47
PA5: J1.12 U2.46
PA6: J1.13 U2.45
PA7: J1.14 U2.44
PTT: Q3.2 X3.1 X3A.1
PTT_DRIVE: R15.1 U2.36
RESET: C5.1 D1.A JP1.6 JP2.5 R5.1 U2.20
RX_AUDIO_OUT: C43.1 J2.1 TP6.TP U8.16 U8.20
RX_AUDIO_RET: J2.2 U7.5
SPI_MISO: J2.14 U2.13 U8.5 U9.3
SPI_MOSI: J2.12 U2.12 U8.4 U9.2
SPI_SCK: J2.10 R4.2 U2.11 U8.3 U9.28
SPI_SS: J2.16 U2.33
SS_ISD: U2.16 U9.1
SS_MX828: U2.10 U8.6
TCK: JP1.1 RN1.1 U2.57
TDI: JP1.9 R12.1 RN1.4 U2.54
TDO: JP1.3 R14.1 RN1.3 U2.55
TMS: JP1.5 RN1.2 U2.56
TX_AUDIO: C52.2 J2.5 R61.2 X3.7 X3A.7
TX_TONE_OUT: C50.1 TP5.TP U8.23
VBATT: C20.1 D7.C R21.1 R23.2 U2.59
VEE_LCD: J1.3 R2.2
VREF: R24.1 U5.3 U10.5 U10.10 U10.13 U10.14
VSQL: C78.+ D10.C R31.1 R37.1 TP3.TP U2.61 U8.9
VTEMP: C19.1 R20.1 R22.2 U2.60
XADC: J2.20 U2.58

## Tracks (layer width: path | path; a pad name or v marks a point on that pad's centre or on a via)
+2V5  (via drill 0.41)
  Top 0.254: U10.1 U10.2 121.28,5.4 120.97,5.71 120.97,6.06 | v120.97,6.67 120.97,6.06 | R46.2 R62.2 R16.2 112.05,13.65 | v111.44,13.65 112.05,13.65 | 112.05,13.65 111.57,13.9 v111.44,13.65 | 112.05,13.65 111.57,13.4 v111.44,13.65 | 120.97,6.06 121.22,6.54 v120.97,6.67 | 120.97,6.06 120.72,6.54 v120.97,6.67
  Bottom 0.254: 120.36,6.67 118.11,6.67 117.79,6.98 117.79,8.89 117.47,9.21 112.08,9.21 111.44,9.84 111.44,13.04 | 120.36,6.67 v120.97,6.67 | 111.44,13.04 v111.44,13.65 | 111.44,13.04 111.69,13.52 v111.44,13.65 | 111.44,13.04 111.19,13.52 v111.44,13.65 | 120.36,6.67 120.84,6.42 v120.97,6.67 | 120.36,6.67 120.84,6.92 v120.97,6.67
+3V3  (via drill 0.41, 0.61)
  Top 0.254: 108.58,51.59 TP2.TP
  Top 0.406: 121.21,46.6 120.97,46.6 120.97,46 | v120.97,45.08 120.97,46 | 120.97,46 120.68,45.19 v120.97,45.08 | 120.97,46 121.25,45.19 v120.97,45.08
  Top 0.61: 121.21,46.6 U4.1 | v108.58,49.85 108.58,50.76 | 108.58,50.76 108.58,51.59 | 108.58,50.76 108.39,49.89 v108.58,49.85 | 108.58,50.76 108.78,49.89 v108.58,49.85
  Top 0.813: C21.+
  Top 1.016: v108.58,49.85 C21.+ v113.35,49.85
  SUPPLY 0.61: v113.35,49.85 114.26,49.85 | 114.26,49.85 120.33,49.85 120.97,49.21 120.97,46 | 120.97,46 v120.97,45.08 | v117.47,29.69 112.71,29.69 111.76,30.64 111.76,49.21 112.39,49.85 112.43,49.85 | 108.58,48.93 108.58,46.67 109.54,45.72 109.54,34.61 107.63,32.7 v107.63,30.8 | 108.58,48.93 v108.58,49.85 | v113.35,49.85 112.43,49.85 | 114.26,49.85 113.39,50.05 v113.35,49.85 | 114.26,49.85 113.39,49.65 v113.35,49.85 | 112.43,49.85 113.3,49.65 v113.35,49.85 | 112.43,49.85 113.3,50.05 v113.35,49.85 | 108.58,48.93 108.78,49.8 v108.58,49.85 | 108.58,48.93 108.39,49.8 v108.58,49.85 | 120.97,46 120.77,45.13 v120.97,45.08 | 120.97,46 121.17,45.13 v120.97,45.08
  pour Top (isolate 0.406, no thermals): 115.57,30.16 116.2,30.8 117.47,30.8 118.43,31.75 118.43,34.61 119.06,34.61 119.06,32.07 119.38,31.75 120.65,31.75 120.97,31.43 120.97,29.21 115.57,29.21
  pour Top (isolate 0.305, no thermals): 107,34.61 107.63,34.61 107.63,32.07 107.95,31.75 109.22,31.75 109.54,31.43 109.54,29.21 104.14,29.21 104.14,30.96 106.68,30.96 107,31.27
+5V  (via drill 0.41, 0.61)
  Top 0.178: R69.2 111.6,27.62 111.44,27.78 R70.2 110.49,27.62 110.33,27.78 110.33,30.19 | R18.2 62.23,44.16 | 62.23,44.16 v62.23,44.77 | 110.33,30.19 v110.33,30.8 | C11.1 32.09,13.97 | 32.09,13.97 v32.7,13.97 | U3.22 27.65,11.11 | v28.26,11.11 27.65,11.11 | 62.23,44.16 62.5,44.6 v62.23,44.77 | 62.23,44.16 61.96,44.6 v62.23,44.77 | 27.65,11.11 28.09,10.84 v28.26,11.11 | 27.65,11.11 28.09,11.38 v28.26,11.11 | 110.33,30.19 110.6,30.63 v110.33,30.8 | 110.33,30.19 110.06,30.63 v110.33,30.8 | 32.09,13.97 32.54,13.7 v32.7,13.97 | 32.09,13.97 32.54,14.24 v32.7,13.97
  Top 0.254: R11.2 | R11.2 | R11.2 49.87,51.12 | 49.87,51.12 v50.48,51.12 | R10.2 49.87,53.02 | 49.87,53.02 v50.48,53.02 | C72.1 99.06,31.14 | 99.06,31.14 v99.06,31.75 | v99.06,31.75 99.06,32.36 | 99.06,32.36 U8.24 | C74.+ 81.92,30.16 81.92,31.46 | 81.92,31.46 v81.92,32.07 | 77.47,26.96 C73.1 C30.2 TP1.TP | 77.47,26.96 v77.47,26.35 | R20.2 61.89,11.11 | 61.89,11.11 v61.28,11.11 | v46.04,54.93 46.65,54.93 | 46.65,54.93 C9.1 | U1.8 45.43,54.93 | 45.43,54.93 v46.04,54.93 | R74.2 133.06,4.13 | 133.06,4.13 v133.67,4.13 | R79.2 40.64,40.96 40.01,41.59 39.97,41.59 | v39.05,41.59 39.97,41.59 | U6.18 80.64,33.65 81.6,33.65 81.92,33.34 81.92,32.68 | v81.92,32.07 81.92,32.68 | U3.26 27.87,13.72 28.26,13.33 28.26,11.72 | 28.26,11.72 v28.26,11.11 | RN1.5 RN1.6 RN1.7 RN1.8 42.41,11.43 | 42.41,11.43 v43.02,11.43 | 49.87,51.12 50.35,50.87 v50.48,51.12 | 49.87,51.12 50.35,51.37 v50.48,51.12 | 49.87,53.02 50.35,52.77 v50.48,53.02 | 49.87,53.02 50.35,53.27 v50.48,53.02 | 99.06,31.14 99.31,31.62 v99.06,31.75 | 99.06,31.14 98.81,31.62 v99.06,31.75 | 99.06,32.36 98.81,31.88 v99.06,31.75 | 99.06,32.36 99.31,31.88 v99.06,31.75 | 77.47,26.96 77.22,26.48 v77.47,26.35 | 77.47,26.96 77.72,26.48 v77.47,26.35 | 81.92,31.46 82.16,31.94 v81.92,32.07 | 81.92,31.46 81.67,31.94 v81.92,32.07 | 81.92,32.68 81.67,32.2 v81.92,32.07 | 81.92,32.68 82.16,32.2 v81.92,32.07 | 61.89,11.11 61.41,11.36 v61.28,11.11 | 61.89,11.11 61.41,10.86 v61.28,11.11 | 28.26,11.72 28.01,11.24 v28.26,11.11 | 28.26,11.72 28.51,11.24 v28.26,11.11 | 46.65,54.93 46.17,55.18 v46.04,54.93 | 46.65,54.93 46.17,54.68 v46.04,54.93 | 45.43,54.93 45.91,54.68 v46.04,54.93 | 45.43,54.93 45.91,55.18 v46.04,54.93 | 133.06,4.13 133.54,3.88 v133.67,4.13
  Top 0.254: 133.06,4.13 133.54,4.38 v133.67,4.13 | 39.97,41.59 39.21,41.94 v39.05,41.59 | 39.97,41.59 39.21,41.25 v39.05,41.59 | 42.41,11.43 42.89,11.18 v43.02,11.43 | 42.41,11.43 42.89,11.68 v43.02,11.43
  Top 0.406: R50.1 65.43,32.38 | 65.43,32.38 v66.04,32.38 | v28.26,11.11 28.87,11.11 | 28.87,11.11 C22.1 | 65.43,32.38 65.97,32.19 v66.04,32.38 | 65.43,32.38 65.97,32.58 v66.04,32.38 | 28.87,11.11 28.32,11.3 v28.26,11.11 | 28.87,11.11 28.32,10.92 v28.26,11.11
  Top 0.61: v20.8,33.65 R7.1
  Top 0.813: R6.1 v39.05,41.59
  Top 1.27: L3.2 v71.44,16.83
  other vias: 87.63,57.47 89.53,59.05 87.63,59.05 89.53,57.47
  pour SUPPLY (isolate 0.305, rank 2, no thermals): 0.95,75.88 0.95,52.7 5.71,52.7 6.03,52.39 6.03,49.85 5.71,49.53 0.95,49.53 0.95,0.95 133.99,0.95 133.99,4.13 arc90 133.67,4.44 arc90 133.35,4.13 133.35,2.86 arc-90 132.08,1.59 76.2,1.59 arc-90 74.93,2.86 74.93,23.81 arc-90 76.2,25.08 102.87,25.08 arc90 103.5,25.72 103.5,26.99 arc-90 104.78,28.26 121.92,28.26 arc90 122.56,28.89 122.56,33.02 arc-90 123.83,34.29 124.78,34.29 arc90 125.41,34.92 arc90 124.78,35.56 123.83,35.56 arc-90 122.56,36.83 122.56,71.12 arc90 121.92,71.75 53.34,71.75 arc90 52.7,71.12 52.7,59.69 arc-90 51.44,58.42 48.26,58.42 arc-90 46.99,59.69 46.99,75.88
  pour Top (isolate 0.61, rank 2, no thermals): 66.67,65.09 66.67,61.59 67.94,60.32 95.25,60.32 95.25,56.51 75.56,56.51 75.56,57.78 68.26,57.78 68.26,56.83 62.87,56.83 62.87,65.09
+12V  (via drill 0.41, 0.61)
  Top 0.254: v111.44,7.3 112.05,7.3 | 112.05,7.3 R73.2 | v118.11,23.81 118.72,23.81 | 118.72,23.81 119.38,23.81 | 119.38,23.81 | 119.38,23.81 C77.1 | U7.8 117.5,23.81 | 117.5,23.81 v118.11,23.81 | 112.05,7.3 111.57,7.55 v111.44,7.3 | 112.05,7.3 111.57,7.05 v111.44,7.3 | 118.72,23.81 118.24,24.06 v118.11,23.81 | 118.72,23.81 118.24,23.56 v118.11,23.81 | 117.5,23.81 117.98,23.56 v118.11,23.81 | 117.5,23.81 117.98,24.06 v118.11,23.81
  Top 0.406: v120.97,7.94 121.58,7.94 | 121.58,7.94 U10.4 124.46,7.94 125.09,7.3 C75.1 | 93.98,13.65 C76.1 | 93.98,13.65 94.96,13.65 | 94.96,13.65 v95.57,13.65 | U5.4 93.66,7.94 93.03,8.57 93.03,11.43 93.98,12.38 93.98,13.65 | U4.3 121.28,49.6 121.28,51.75 121.76,52.23 122.91,52.23 | 122.91,52.23 v123.83,52.23 | 121.58,7.94 121.03,8.13 v120.97,7.94 | 121.58,7.94 121.03,7.75 v120.97,7.94 | 94.96,13.65 95.5,13.46 v95.57,13.65 | 94.96,13.65 95.5,13.84 v95.57,13.65 | 122.91,52.23 123.72,51.94 v123.83,52.23 | 122.91,52.23 123.72,52.52 v123.83,52.23
  other vias: 50.01,63.18 50.01,61.59 50.01,60.01
  pour Top (isolate 0.61, rank 5, no thermals): 27.3,61.59 27.3,57.78 59.05,57.78 59.69,57.15 59.69,54.61 60.96,54.61 60.96,67.94 61.59,68.58 66.36,68.58 66.36,69.85 60.01,69.85 58.74,68.58 58.74,64.77 58.1,64.13 41.91,64.13 41.27,64.77 41.27,69.85 40.32,70.8 36.2,70.8 36.2,69.85 39.05,69.85 39.37,69.53 39.37,62.23 38.73,61.59
  pour SUPPLY (isolate 0.305, rank 3, no thermals): 47.62,75.88 47.62,59.69 arc90 48.26,59.05 51.44,59.05 arc90 52.07,59.69 52.07,71.12 arc-90 53.34,72.39 121.92,72.39 arc-90 123.19,71.12 123.19,36.83 arc90 123.83,36.19 124.78,36.19 arc-90 126.05,34.92 arc-90 124.78,33.65 123.83,33.65 arc90 123.19,33.02 123.19,28.89 arc-90 121.92,27.62 104.78,27.62 arc90 104.14,26.99 104.14,25.72 arc-90 102.87,24.45 76.2,24.45 arc90 75.56,23.81 75.56,2.86 arc90 76.2,2.22 132.08,2.22 arc90 132.72,2.86 132.72,4.13 arc-90 133.67,5.08 arc-90 134.62,4.13 134.62,0.95 153.35,0.95 153.35,75.88
AGND  (via drill 0.41, 0.61)
  Top 0.178: 37.31,22.07 U12.2 | v34.61,26.99
  Top 0.254: C57.2 84.75,27.62 | 84.75,27.62 v84.14,27.62 | v111.44,4.13 112.05,4.13 | 112.05,4.13 R77.1 | U7.4 109.83,20 | 109.83,20 v109.22,20 | C66.2 137.5,4.13 | 137.5,4.13 v138.11,4.13 | R78.1 125.39,4.13 | 125.39,4.13 v124.78,4.13 | C77.2 122.26,23.49 | 122.26,23.49 v122.87,23.49 | C65.2 110.83,4.13 | 110.83,4.13 v111.44,4.13 | C76.2 92.71,13.33 | U5.11 92.39,7.94 92.87,7.46 92.87,7.28 | 92.87,7.28 v92.87,6.67 | C8.2 35.22,26.99 | 35.22,26.99 v34.61,26.99 | R33.1 106.39,16.83 | 106.39,16.83 v107,16.83 | R38.2 79.08,10.48 | 79.08,10.48 v79.69,10.48 | C38.1 87.97,7.3 | 87.97,7.3 v88.58,7.3 | R39.2 84.75,10.48 | 84.75,10.48 v84.14,10.48 | R40.2 80.3,4.13 | 80.3,4.13 v79.69,4.13 | D10.A 87.02,20.48 | 87.02,20.48 v87.63,20.48 | C19.2 70.19,11.11 | 70.19,11.11 v70.8,11.11 | C19.2 C19.2 arc-270 C19.2 | C19.2 R22.1 | R66.1 140.52,25.53 141.29,24.76 141.29,23.49 141.6,23.18 C60.2 R67.2 | C78.- 80.03,20.48 | 80.03,20.48 v80.64,20.48 | R71.1 149.19,4.13 C62.2 | R37.2 87.63,16.83 87.63,19.87 | v87.63,20.48 87.63,19.87 | 84.75,27.62 84.27,27.87 v84.14,27.62 | 84.75,27.62 84.27,27.37 v84.14,27.62 | 112.05,4.13 111.57,4.38 v111.44,4.13 | 112.05,4.13 111.57,3.88 v111.44,4.13 | 110.83,4.13 111.31,3.88 v111.44,4.13 | 110.83,4.13 111.31,4.38 v111.44,4.13 | 70.19,11.11 70.67,10.86 v70.8,11.11 | 70.19,11.11 70.67,11.36 v70.8,11.11 | 109.83,20 109.35,20.25 v109.22,20 | 109.83,20 109.35,19.75 v109.22,20 | 137.5,4.13 137.98,3.88 v138.11,4.13 | 137.5,4.13 137.98,4.38 v138.11,4.13 | 125.39,4.13 124.91,4.38 v124.78,4.13 | 125.39,4.13 124.91,3.88 v124.78,4.13 | 122.26,23.49 122.74,23.25 v122.87,23.49 | 122.26,23.49 122.74,23.74 v122.87,23.49 | 92.87,7.28 92.62,6.8 v92.87,6.67 | 92.87,7.28 93.12,6.8 v92.87,6.67
  Top 0.254: 35.22,26.99 34.74,27.24 v34.61,26.99 | 35.22,26.99 34.74,26.74 v34.61,26.99 | 106.39,16.83 106.87,16.58 v107,16.83 | 106.39,16.83 106.87,17.08 v107,16.83 | 79.08,10.48 79.56,10.23 v79.69,10.48 | 79.08,10.48 79.56,10.73 v79.69,10.48 | 87.97,7.3 88.45,7.05 v88.58,7.3 | 87.97,7.3 88.45,7.55 v88.58,7.3 | 80.3,4.13 79.82,4.38 v79.69,4.13 | 80.3,4.13 79.82,3.88 v79.69,4.13 | 84.75,10.48 84.27,10.73 v84.14,10.48 | 84.75,10.48 84.27,10.23 v84.14,10.48 | 87.02,20.48 87.5,20.23 v87.63,20.48 | 87.02,20.48 87.5,20.73 v87.63,20.48 | 87.63,19.87 87.88,20.35 v87.63,20.48 | 87.63,19.87 87.38,20.35 v87.63,20.48 | 80.03,20.48 80.52,20.23 v80.64,20.48 | 80.03,20.48 80.52,20.73 v80.64,20.48
  Top 0.406: 83.82,50.82 C56.- | 83.82,50.82 v83.82,51.43 | U9.23 113.67,32.36 | 113.67,32.36 v113.67,31.75 | C63.1 102.23,26.96 | 102.23,26.96 v102.23,26.35 | v115.89,7.94 116.5,7.94 | 116.5,7.94 U10.11 | v91.12,13.65 91.73,13.65 | 91.73,13.65 C76.2 | C75.2 128.61,7.3 | 128.61,7.3 v129.22,7.3 | C55.- 87.63,50.82 | 87.63,50.82 v87.63,51.43 | R23.1 C20.2 62.52,54.93 | v61.91,54.93 62.52,54.93 | D7.A 57.81,55.88 | 57.81,55.88 v58.42,55.88 | 83.82,50.82 84.01,51.37 v83.82,51.43 | 83.82,50.82 83.63,51.37 v83.82,51.43 | 113.67,32.36 113.47,31.82 v113.67,31.75 | 113.67,32.36 113.86,31.82 v113.67,31.75 | 102.23,26.96 102.04,26.42 v102.23,26.35 | 102.23,26.96 102.43,26.42 v102.23,26.35 | 116.5,7.94 115.95,8.13 v115.89,7.94 | 116.5,7.94 115.95,7.75 v115.89,7.94 | 91.73,13.65 91.19,13.84 v91.12,13.65 | 91.73,13.65 91.19,13.46 v91.12,13.65 | 128.61,7.3 129.16,7.11 v129.22,7.3 | 128.61,7.3 129.16,7.49 v129.22,7.3 | 87.63,50.82 87.82,51.37 v87.63,51.43 | 87.63,50.82 87.44,51.37 v87.63,51.43 | 62.52,54.93 61.98,55.12 v61.91,54.93 | 62.52,54.93 61.98,54.74 v61.91,54.93 | 57.81,55.88 58.35,55.69 v58.42,55.88 | 57.81,55.88 58.35,56.07 v58.42,55.88
  Top 0.61: C4.1 v34.61,24.92 34.61,22.54 | v42.86,56.83 52.39,56.83 53.34,55.88 D7.A | 34.61,22.54 C79.- | 37.31,22.07 34.61,22.07 34.61,22.54 | C79.- 34.61,22.54 | C79.-
  Bottom 0.406: 61.3,54.93 60.96,54.93 60.01,55.88 59.03,55.88 | 61.3,54.93 v61.91,54.93 | v58.42,55.88 59.03,55.88 | 61.3,54.93 61.84,54.74 v61.91,54.93 | 61.3,54.93 61.84,55.12 v61.91,54.93 | 59.03,55.88 58.49,56.07 v58.42,55.88 | 59.03,55.88 58.49,55.69 v58.42,55.88
  other vias: 106.68,44.77 117.47,26.67 140.97,49.85 140.97,37.46 134.94,28.57 128.27,20.32 129.86,31.11 152.4,31.75 152.4,2.54 99.38,69.21 99.38,67.94 70.8,6.67 70.8,2.22 109.22,25.72
  pour GROUND (isolate 0.305, rank 3, no thermals): 81.28,60.64 81.28,48.26 arc90 81.92,47.62 104.14,47.62 arc-90 105.41,46.35 105.41,44.45 arc90 106.05,43.81 112.08,43.81 arc90 112.71,44.45 112.71,46.51 arc-90 113.98,47.78 121.6,47.78 arc-90 122.87,46.51 122.87,34.29 arc90 123.51,33.65 124.78,33.65 arc-90 126.05,32.38 126.05,32.38 arc-90 124.78,31.11 123.51,31.11 arc90 122.87,30.48 122.87,28.89 arc-90 121.6,27.62 115.57,27.62 arc-90 114.3,28.89 114.3,31.59 arc90 113.67,32.23 arc90 113.03,31.59 113.03,28.1 arc-90 111.76,26.83 102.23,26.83 arc90 101.6,26.19 101.6,25.72 arc-90 100.33,24.45 86.04,24.45 arc-90 84.77,25.72 84.77,27.62 arc180 83.5,27.62 83.5,25.72 arc-90 82.23,24.45 76.36,24.45 arc90 75.72,23.81 75.72,13.02 arc-90 74.45,11.75 70.48,11.75 arc90 69.85,11.11 69.85,0.95 153.35,0.95 153.35,75.88 93.03,75.88 93.03,62.55 arc-90 91.76,61.28 81.92,61.28 arc90 81.28,60.64
  pour Top (isolate 0.61, rank 3, no thermals): 121.28,50.8 121.28,38.42 122.56,37.15 122.56,18.1 138.11,18.1 138.11,28.42 142.24,28.42 142.24,50.8 141.6,51.43 140.34,51.43 139.7,52.07 139.7,59.69 140.34,60.32 144.15,60.32 147,57.47 147,49.21 152.08,49.21 152.72,48.58 152.72,32.7 151.76,32.07 151.76,31.43 152.72,30.48 152.72,4.13 150.81,2.22 74.93,2.22 73.98,3.17 73.98,13.97 72.71,13.97 72.39,14.29 72.39,15.24 70.17,15.24 70.17,1.59 153.35,1.59 153.35,75.25 144.3,75.25 144.3,61.91 143.99,61.59 133.67,61.59 133.35,61.28 133.35,50.8
  pour Bottom (isolate 0.61, rank 2, no thermals): 34.92,75.25 34.92,28.26 33.97,27.3 33.97,23.34 34.29,23.02 38.42,23.02 38.42,35.24 42.23,35.24 42.23,54.61 44.77,57.15 49.53,57.15 58.42,66.04 116.84,66.04 120.65,62.23 120.65,51.12 128.27,51.12 128.27,36.19 127.95,35.88 126.68,35.88 126.36,35.56 126.36,34.29 126.68,33.97 127.95,33.97 128.27,33.65 128.27,28.26 126.36,28.26 126.36,25.08 123.19,25.08 122.24,24.13 122.24,19.37 129.54,19.37 130.49,18.41 136.21,18.41 136.21,16.19 142.88,16.19 142.88,8.25 139.06,8.25 139.06,7.3 129.86,7.3 129.54,7.62 128.91,7.62 128.59,7.3 122.56,7.3 120.02,4.76 110.49,4.76 109.54,5.71 105.41,5.71 102.87,3.17 80.96,3.17 78.11,6.03 78.11,8.57 70.17,8.57 70.17,1.59 153.35,1.59 153.35,75.25
  pour Top (isolate 0.61, no thermals): 104.78,47.31 107.31,47.31 107.63,46.99 107.63,42.23 105.73,42.23 105.73,44.77 105.41,45.08 105.09,45.08 104.78,45.4
  pour Top (isolate 0.406, rank 2, no thermals): 115.25,27.94 120.97,27.94 120.97,25.72 113.35,25.72 112.71,25.08 107,25.08 107,25.4 107.95,26.35 114.94,26.35 115.25,26.67
  pour Top (no thermals): 97.47,69.21 98.11,69.85 100.01,69.85 100.01,67.31 98.11,67.31 97.47,67.94
AUX_AUDIO  (via drill 0.41)
  Top 0.254: X3.8 142.88,53.34 142.88,43.81 | v142.88,21.59 142.88,22.2 | 142.88,22.2 142.88,35.58 | 142.88,35.58 v142.88,36.19 | v142.88,36.19 142.88,36.8 | 142.88,36.8 142.88,43.81 | C45.2 124.17,13.65 | 124.17,13.65 v124.78,13.65 | 142.88,43.81 R49.2 | 142.88,35.58 143.12,36.07 v142.88,36.19 | 142.88,35.58 142.63,36.07 v142.88,36.19 | 142.88,36.8 142.63,36.32 v142.88,36.19 | 142.88,36.8 143.12,36.32 v142.88,36.19 | 142.88,22.2 142.63,21.72 v142.88,21.59 | 142.88,22.2 143.12,21.72 v142.88,21.59 | 124.17,13.65 124.65,13.4 v124.78,13.65 | 124.17,13.65 124.65,13.9 v124.78,13.65
  Bottom 0.254: 142.88,20.98 142.88,15.87 142.24,15.24 127.32,15.24 125.73,13.65 125.39,13.65 | 142.88,20.98 v142.88,21.59 | v124.78,13.65 125.39,13.65 | J2.3 130.81,29.84 137.16,36.19 142.26,36.19 | v142.88,36.19 142.26,36.19 | 142.26,36.19 142.75,35.95 v142.88,36.19 | 142.26,36.19 142.75,36.44 v142.88,36.19 | 142.88,20.98 143.12,21.46 v142.88,21.59 | 142.88,20.98 142.63,21.46 v142.88,21.59 | 125.39,13.65 124.91,13.9 v124.78,13.65 | 125.39,13.65 124.91,13.4 v124.78,13.65
  Bottom 0.61: X3.8 X3A.8
AUX_AUDIO_OUT  (via drill 0.41)
  Top 0.254: v96.52,31.75 96.52,32.36 | 96.52,32.36 U8.22 | v109.22,23.81 109.83,23.81 | 109.83,23.81 U7.1 | v109.22,23.81 108.61,23.81 | 108.61,23.81 TP4.TP | 96.52,32.36 96.27,31.88 v96.52,31.75 | 96.52,32.36 96.77,31.88 v96.52,31.75 | 109.83,23.81 109.35,24.06 v109.22,23.81 | 109.83,23.81 109.35,23.56 v109.22,23.81 | 108.61,23.81 109.09,23.56 v109.22,23.81 | 108.61,23.81 109.09,24.06 v109.22,23.81
  Bottom 0.254: 96.52,31.14 96.52,24.76 97.47,23.81 108.61,23.81 | 96.52,31.14 v96.52,31.75 | 108.61,23.81 v109.22,23.81 | 96.52,31.14 96.77,31.62 v96.52,31.75 | 96.52,31.14 96.27,31.62 v96.52,31.75 | 108.61,23.81 109.09,23.56 v109.22,23.81 | 108.61,23.81 109.09,24.06 v109.22,23.81
AVR_5V  (via drill 0.41, 0.61)
  Top 0.178: D1.C C1.1 | U2.52 40.11,31.22 39.85,30.96 C2.1
  Top 0.254: R5.2 C1.1 60.96,20.95 60.64,20.95 | 57.01,24.84 U2.21 | U2.52 42.34,31.22 42.59,31.48 | v43.02,31.91 42.59,31.48 | 42.59,31.48 43.11,31.64 v43.02,31.91 | 42.59,31.48 42.76,31.99 v43.02,31.91
  Top 0.406: R5.2 59.05,16.83 | v55.56,24.84 56.17,24.84 | 56.17,24.84 57.01,24.84 | 56.17,24.84 55.63,25.04 v55.56,24.84 | 56.17,24.84 55.63,24.65 v55.56,24.84
  Top 0.813: L2.2 60.64,20.95 v60.64,22.7
  SUPPLY 0.406: v60.64,22.7 59.73,22.7 | 59.73,22.7 56.2,22.7 55.56,23.34 55.56,24.23 | 55.56,24.23 v55.56,24.84 | v55.56,24.84 54.95,24.84 | 54.95,24.84 53.42,24.84 46.35,31.91 43.63,31.91 | 43.63,31.91 v43.02,31.91 | 59.73,22.7 60.54,22.41 v60.64,22.7 | 59.73,22.7 60.54,22.99 v60.64,22.7 | 55.56,24.23 55.75,24.78 v55.56,24.84 | 55.56,24.23 55.37,24.78 v55.56,24.84 | 54.95,24.84 55.49,24.65 v55.56,24.84 | 54.95,24.84 55.49,25.04 v55.56,24.84 | 43.63,31.91 43.09,32.1 v43.02,31.91 | 43.63,31.91 43.09,31.72 v43.02,31.91
AVR_REF
  Top 0.178: 39.21,21.75 U12.1
  Top 0.254: C4.2 37.78,23.49 38.1,23.18 38.89,23.18 39.21,22.86 39.21,21.75 | U2.64 41.41,21.75 39.21,21.75 | 39.21,21.75 | 39.21,21.75 U12.1
B_CTS
  Top 0.178: U3.6 19.34,11.77 19.05,12.06 7.62,12.06 6.67,13.02 6.67,17.46 6.87,17.67 X2.8
B_DCD
  Top 0.178: X2.1 12.72,24.59 13.49,23.81 13.49,20.32 13.81,20 21.59,20 22.86,18.73 22.86,11.27 22.06,10.47 U3.8
B_DSR
  Top 0.178: X2.6 12.36,23.2 13.02,22.54 13.02,20.16 13.65,19.53 21.43,19.53 22.38,18.57 22.38,11.75 21.76,11.12 U3.7
B_DTR  (via drill 0.41)
  Top 0.178: U3.10 18.29,9.17 18.1,9.37 18.1,10.03 | v18.1,10.64 18.1,10.03 | 18.1,10.03 18.37,10.47 v18.1,10.64 | 18.1,10.03 17.83,10.47 v18.1,10.64
  Bottom 0.178: X2.4 17.53,16.28 18.1,15.72 18.1,11.25 | 18.1,11.25 v18.1,10.64 | 18.1,11.25 17.83,10.8 v18.1,10.64 | 18.1,11.25 18.37,10.8 v18.1,10.64
B_RI
  Top 0.178: U3.4 19.58,13.07 19.05,12.54 12.7,12.54 12.38,12.86 12.38,14.6 12.09,14.9 X2.9
B_RTS
  Top 0.178: X2.7 6.46,20.43 5.71,19.68 5.71,12.7 7.3,11.11 16.83,11.11 17.14,10.79 17.14,8.89 17.52,8.52 U3.11
B_RXD
  Top 0.178: X2.2 12.15,21.82 12.54,21.43 12.54,20 13.49,19.05 21.27,19.05 21.91,18.41 21.91,12.7 21.63,12.42 U3.5
B_TXD
  Top 0.178: X2.3 6.67,19.05 6.19,18.57 6.19,12.86 7.46,11.59 18.73,11.59 19.05,11.27 19.05,10.16 19.39,9.82 U3.9
BEEP_PWM  (via drill 0.41)
  Top 0.178: v73.66,16.83 74.27,16.83 | 74.27,16.83 R68.1 | v73.66,16.83 73.66,16.22 | 73.66,16.22 TP7.TP | U2.15 54.41,18.93 55.24,18.1 55.24,17.91 | 55.24,17.91 v55.24,17.3 | 74.27,16.83 73.83,17.1 v73.66,16.83 | 74.27,16.83 73.83,16.56 v73.66,16.83 | 73.66,16.22 73.93,16.66 v73.66,16.83 | 73.66,16.22 73.39,16.66 v73.66,16.83 | 55.24,17.91 54.97,17.47 v55.24,17.3 | 55.24,17.91 55.52,17.47 v55.24,17.3
  Bottom 0.178: v55.24,17.3 55.85,17.3 | 55.85,17.3 66.99,17.3 68.26,18.57 73.34,18.57 73.66,18.26 73.66,17.44 | 73.66,17.44 v73.66,16.83 | 73.66,17.44 73.39,16.99 v73.66,16.83 | 73.66,17.44 73.93,16.99 v73.66,16.83 | 55.85,17.3 55.41,17.57 v55.24,17.3 | 55.85,17.3 55.41,17.03 v55.24,17.3
CGND  (via drill 0.61)
  Top 0.178: R13.2 111.12,53.97 110.81,54.29
  Bottom 0.61: X3.4 X3A.4
  other vias: 94.3,69.21 94.3,67.94
  pour Top (isolate 0.61, rank 6, no thermals): 12.7,75.25 12.7,70.48 15.56,70.48 15.88,70.17 15.88,64.77 17.14,64.77 17.78,65.41 17.78,72.39 18.41,73.02 30.8,73.02 31.43,72.39 31.43,69.85 33.66,69.85 33.97,69.53 33.97,66.04 34.29,65.72 35.56,65.72 35.88,65.41 35.88,62.86 37.78,62.86 37.78,68.58 37.47,68.9 35.88,68.9 35.56,69.21 35.56,71.75 35.88,72.07 40.96,72.07 42.23,70.8 58.74,70.8 59.37,71.44 69.22,71.44 69.85,70.8 69.85,61.91 70.48,61.28 95.89,61.28 96.52,60.64 96.52,56.51 110.17,56.51 110.17,53.66 111.44,53.66 111.44,56.51 122.56,56.51 122.56,53.66 124.14,53.66 124.78,53.02 124.78,51.43 132.08,51.43 132.08,61.91 133.03,62.86 143.19,62.86 143.19,64.13 129.86,64.13 126.36,60.64 101.92,60.64 101.92,75.25
COM_CTS  (via drill 0.41)
  Top 0.178: U3.17 24.2,7.87 23.93,8.14 | v23.5,8.57 23.93,8.14 | U2.14 53.61,17.89 53.34,17.62 53.16,17.62 | 53.16,17.62 v52.55,17.62 | 23.93,8.14 23.8,8.65 v23.5,8.57 | 23.93,8.14 23.42,8.26 v23.5,8.57 | 53.16,17.62 52.71,17.89 v52.55,17.62 | 53.16,17.62 52.71,17.35 v52.55,17.62
  Bottom 0.178: 23.5,9.18 23.5,15.87 23.97,16.35 47.15,16.35 49.05,18.26 50.64,18.26 51.28,17.62 51.94,17.62 | 23.5,9.18 v23.5,8.57 | v52.55,17.62 51.94,17.62 | 23.5,9.18 23.22,8.74 v23.5,8.57 | 23.5,9.18 23.77,8.74 v23.5,8.57 | 51.94,17.62 52.38,17.35 v52.55,17.62 | 51.94,17.62 52.38,17.89 v52.55,17.62
COM_DCD  (via drill 0.41)
  Top 0.178: U2.8 48.81,18.18 49.1,17.89 | 49.1,17.89 v49.53,17.46 | v27.78,9.37 27.78,8.76 | 27.78,8.76 27.78,6.98 27.37,6.57 U3.15 | 49.1,17.89 49.22,17.39 v49.53,17.46 | 49.1,17.89 49.6,17.77 v49.53,17.46 | 27.78,8.76 28.05,9.2 v27.78,9.37 | 27.78,8.76 27.51,9.2 v27.78,9.37
  Bottom 0.178: v49.53,17.46 49.53,16.85 | 49.53,16.85 49.53,16.51 50.16,15.87 50.16,14.29 49.85,13.97 47.62,13.97 46.67,14.92 27.3,14.92 26.99,14.6 26.99,10.95 27.78,10.16 27.78,9.98 | 27.78,9.98 v27.78,9.37 | 49.53,16.85 49.8,17.3 v49.53,17.46 | 49.53,16.85 49.26,17.3 v49.53,17.46 | 27.78,9.98 27.51,9.53 v27.78,9.37 | 27.78,9.98 28.05,9.53 v27.78,9.37
COM_DSR  (via drill 0.41)
  Top 0.178: U3.16 23.74,7.22 23.02,7.94 22.84,7.94 | v22.23,7.94 22.84,7.94 | U2.17 56.67,21.62 56.67,19.21 56.04,18.57 56.04,16.51 55.72,16.19 53.63,16.19 | 53.63,16.19 v53.02,16.19 | 53.63,16.19 53.19,16.46 v53.02,16.19 | 53.63,16.19 53.19,15.92 v53.02,16.19 | 22.84,7.94 22.39,8.21 v22.23,7.94 | 22.84,7.94 22.39,7.67 v22.23,7.94
  Bottom 0.178: v53.02,16.19 53.5,16.67 53.5,18.57 53.18,18.89 48.74,18.89 46.83,16.99 22.86,16.99 22.23,16.35 22.23,8.55 | 22.23,8.55 v22.23,7.94 | v53.02,16.19 52.95,16.5 53.45,16.62 53.33,16.12 v53.02,16.19 | 22.23,8.55 21.95,8.1 v22.23,7.94 | 22.23,8.55 22.5,8.1 v22.23,7.94
COM_DTR  (via drill 0.41)
  Top 0.178: U2.35 53.61,40.91 54.81,42.11 | v55.24,42.54 54.81,42.11 | 61.89,33.97 62.23,33.97 62.87,34.61 67.63,34.61 68.42,33.81 68.61,33.81 | 61.89,33.97 v61.28,33.97 | v69.22,33.81 68.61,33.81 | 20.64,7.22 22.94,7.22 23.65,6.51 23.65,6.32 | v23.65,5.71 23.65,6.32 | U3.12 20.64,7.87 20.64,7.22 | 20.64,7.22 U3.13 | 54.81,42.11 55.32,42.24 v55.24,42.54 | 54.81,42.11 54.94,42.62 v55.24,42.54 | 61.89,33.97 61.44,34.24 v61.28,33.97 | 61.89,33.97 61.44,33.7 v61.28,33.97 | 68.61,33.81 69.05,33.54 v69.22,33.81 | 68.61,33.81 69.05,34.08 v69.22,33.81 | 23.65,6.32 23.38,5.88 v23.65,5.71 | 23.65,6.32 23.93,5.88 v23.65,5.71
  Bottom 0.178: 69.22,34.42 69.22,36.19 69.85,36.83 82.55,36.83 83.19,36.19 83.19,25.72 82.55,25.08 78.11,25.08 77.47,24.45 77.47,10.48 76.83,9.84 59.37,9.84 56.83,12.38 30,12.38 29.69,12.06 29.69,9.05 26.35,5.71 24.26,5.71 | 69.22,34.42 v69.22,33.81 | 55.85,42.54 57.63,42.54 58.42,41.75 60.64,41.75 61.28,41.12 61.28,34.58 | 55.85,42.54 v55.24,42.54 | v61.28,33.97 61.28,34.13 61.28,34.58 | 24.26,5.71 v23.65,5.71 | 55.85,42.54 55.41,42.82 v55.24,42.54 | 55.85,42.54 55.41,42.27 v55.24,42.54 | 61.28,34.58 61.01,34.14 v61.28,33.97 | 61.28,34.58 61.55,34.14 v61.28,33.97 | 69.22,34.42 68.94,33.98 v69.22,33.81 | 69.22,34.42 69.49,33.98 v69.22,33.81 | 24.26,5.71 23.82,5.99 v23.65,5.71 | 24.26,5.71 23.82,5.44 v23.65,5.71
COM_RXD  (via drill 0.41)
  Top 0.178: v49.21,14.92 49.21,14.31 | 49.21,14.31 R3.2 | 49.21,15.53 49.21,15.56 48.9,15.87 44.77,15.87 44.01,16.63 U2.2 | 49.21,15.53 v49.21,14.92 | v24.77,8.89 25.38,8.89 | 25.38,8.89 25.4,8.89 25.77,8.52 U3.18 | 49.21,14.31 49.48,14.76 v49.21,14.92 | 49.21,14.31 48.94,14.76 v49.21,14.92 | 49.21,15.53 48.94,15.09 v49.21,14.92 | 49.21,15.53 49.48,15.09 v49.21,14.92 | 25.38,8.89 24.93,9.16 v24.77,8.89 | 25.38,8.89 24.93,8.62 v24.77,8.89
  Bottom 0.178: v49.21,14.92 48.6,14.92 | 48.6,14.92 47.94,14.92 47.15,15.72 26.35,15.72 26.04,15.4 26.04,9.21 25.72,8.89 25.38,8.89 | 25.38,8.89 v24.77,8.89 | 48.6,14.92 49.05,14.65 v49.21,14.92 | 48.6,14.92 49.05,15.19 v49.21,14.92 | 25.38,8.89 24.93,9.16 v24.77,8.89 | 25.38,8.89 24.93,8.62 v24.77,8.89
COM_TXD  (via drill 0.41)
  Top 0.178: R1.2 51.75,14.6 50.8,15.56 50.8,15.9 | v50.8,16.51 50.8,15.9 | v50.8,16.51 50.19,16.51 | 50.19,16.51 45.24,16.51 44.81,16.94 U2.3 | U3.14 22,6.57 22.23,6.35 22.23,6.32 | v22.23,5.71 22.23,6.32 | 22.23,6.32 21.95,5.88 v22.23,5.71 | 22.23,6.32 22.5,5.88 v22.23,5.71 | 50.8,15.9 51.07,16.34 v50.8,16.51 | 50.8,15.9 50.53,16.34 v50.8,16.51 | 50.19,16.51 50.63,16.24 v50.8,16.51 | 50.19,16.51 50.63,16.78 v50.8,16.51
  Bottom 0.178: v50.8,16.51 50.8,15.9 | 50.8,15.9 50.8,13.81 50.01,13.02 29.69,13.02 29.05,12.38 29.05,9.21 26.83,6.98 22.54,6.98 22.23,6.67 22.23,6.32 | 22.23,6.32 v22.23,5.71 | 22.23,6.32 21.95,5.88 v22.23,5.71 | 22.23,6.32 22.5,5.88 v22.23,5.71 | 50.8,15.9 51.07,16.34 v50.8,16.51 | 50.8,15.9 50.53,16.34 v50.8,16.51
COS  (via drill 0.41)
  Top 0.178: 120.97,54.95 120.97,53.66 119.38,52.07 R13.1 111.42,52.07 | 120.97,54.95 v120.97,55.56 | v110.81,52.07 111.42,52.07 | R19.2 66.67,50.82 | 66.67,50.82 v66.67,51.43 | 120.97,54.95 121.24,55.4 v120.97,55.56 | 120.97,54.95 120.7,55.4 v120.97,55.56 | 66.67,50.82 66.95,51.27 v66.67,51.43 | 66.67,50.82 66.4,51.27 v66.67,51.43 | 111.42,52.07 110.97,52.34 v110.81,52.07 | 111.42,52.07 110.97,51.8 v110.81,52.07
  Bottom 0.178: v120.97,55.56 120.97,56.17 | 120.97,56.17 120.97,65.41 121.6,66.04 X3.3 | 110.2,52.07 102.87,52.07 100.97,53.97 66.99,53.97 66.67,53.66 66.67,52.04 | 110.2,52.07 v110.81,52.07 | v66.67,51.43 66.67,52.04 | 120.97,56.17 120.7,55.73 v120.97,55.56 | 120.97,56.17 121.24,55.73 v120.97,55.56 | 66.67,52.04 66.4,51.6 v66.67,51.43 | 66.67,52.04 66.95,51.6 v66.67,51.43 | 110.2,52.07 110.64,51.8 v110.81,52.07 | 110.2,52.07 110.64,52.34 v110.81,52.07
  Bottom 0.61: X3.3 X3A.3
CS_DTMF  (via drill 0.41)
